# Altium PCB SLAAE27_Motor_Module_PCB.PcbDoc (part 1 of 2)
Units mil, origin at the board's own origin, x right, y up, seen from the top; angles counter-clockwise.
Board outline 2500 x 2000 mil, 4 copper layers (L1-Top Layer, L2-GND, L3-PWR, L4-Bottom Layer), stack 61.634 mil thick; 168 components, 85 nets, 418 pads, 206 vias.
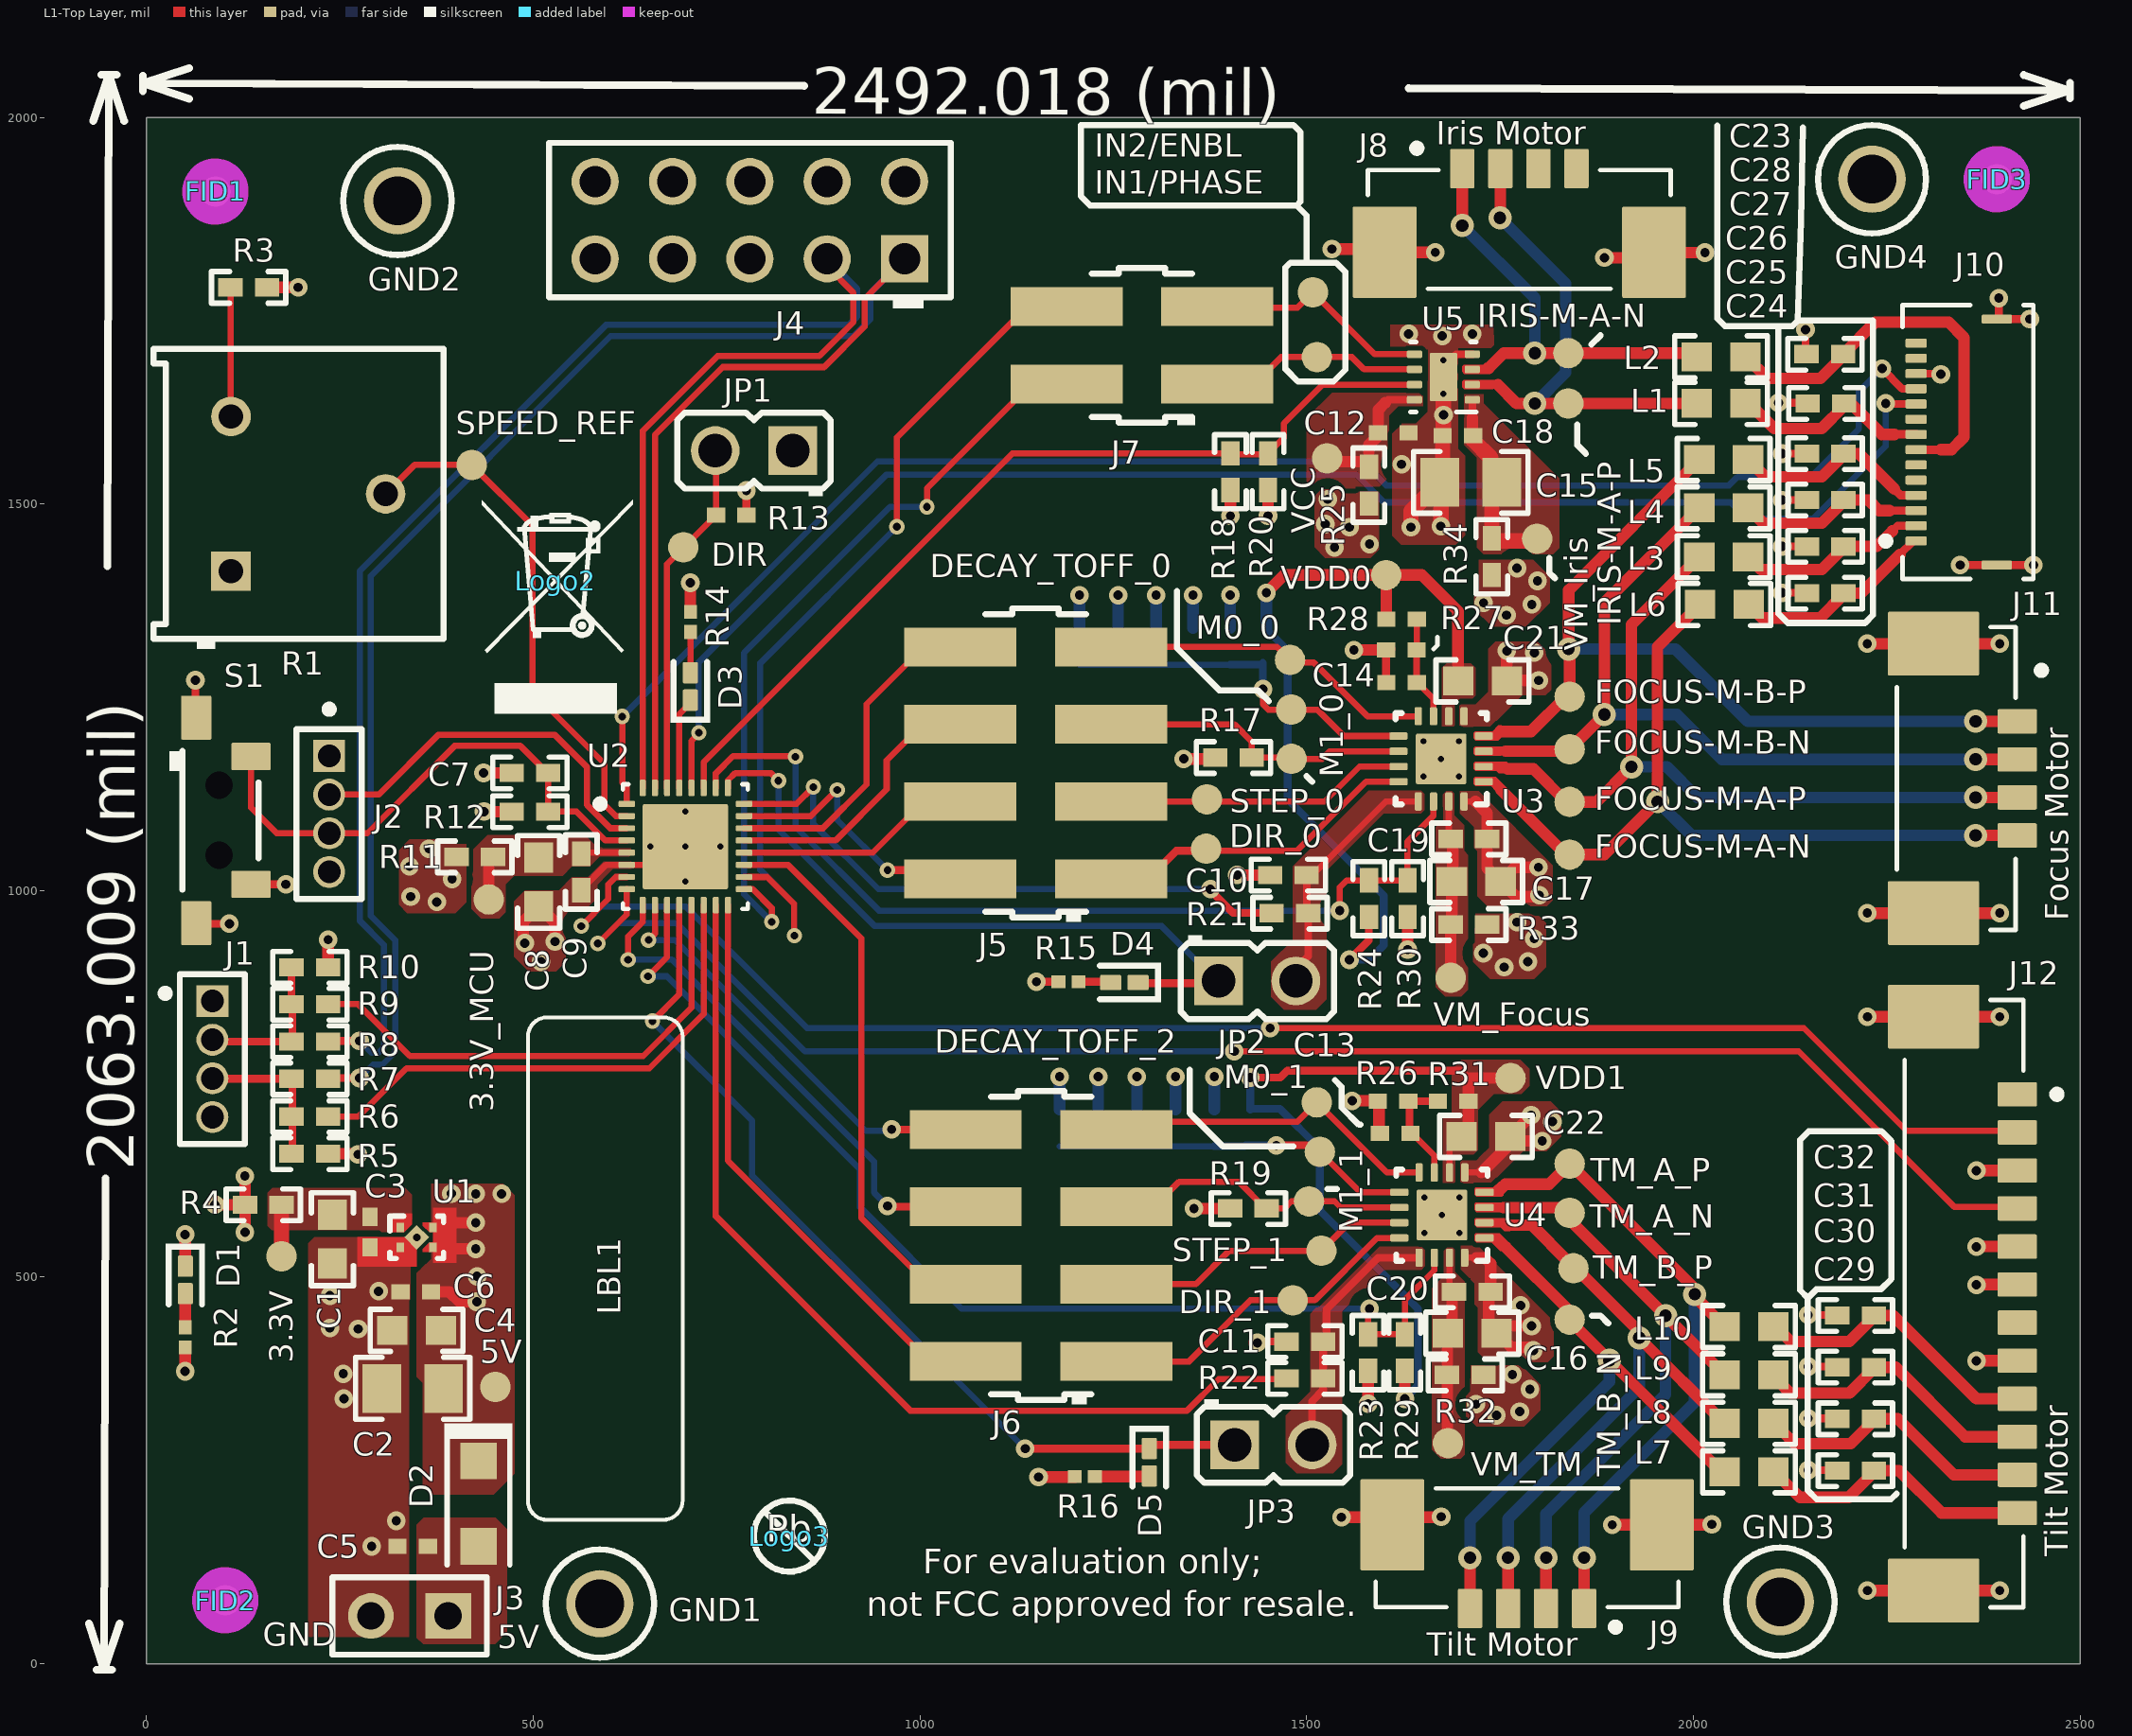
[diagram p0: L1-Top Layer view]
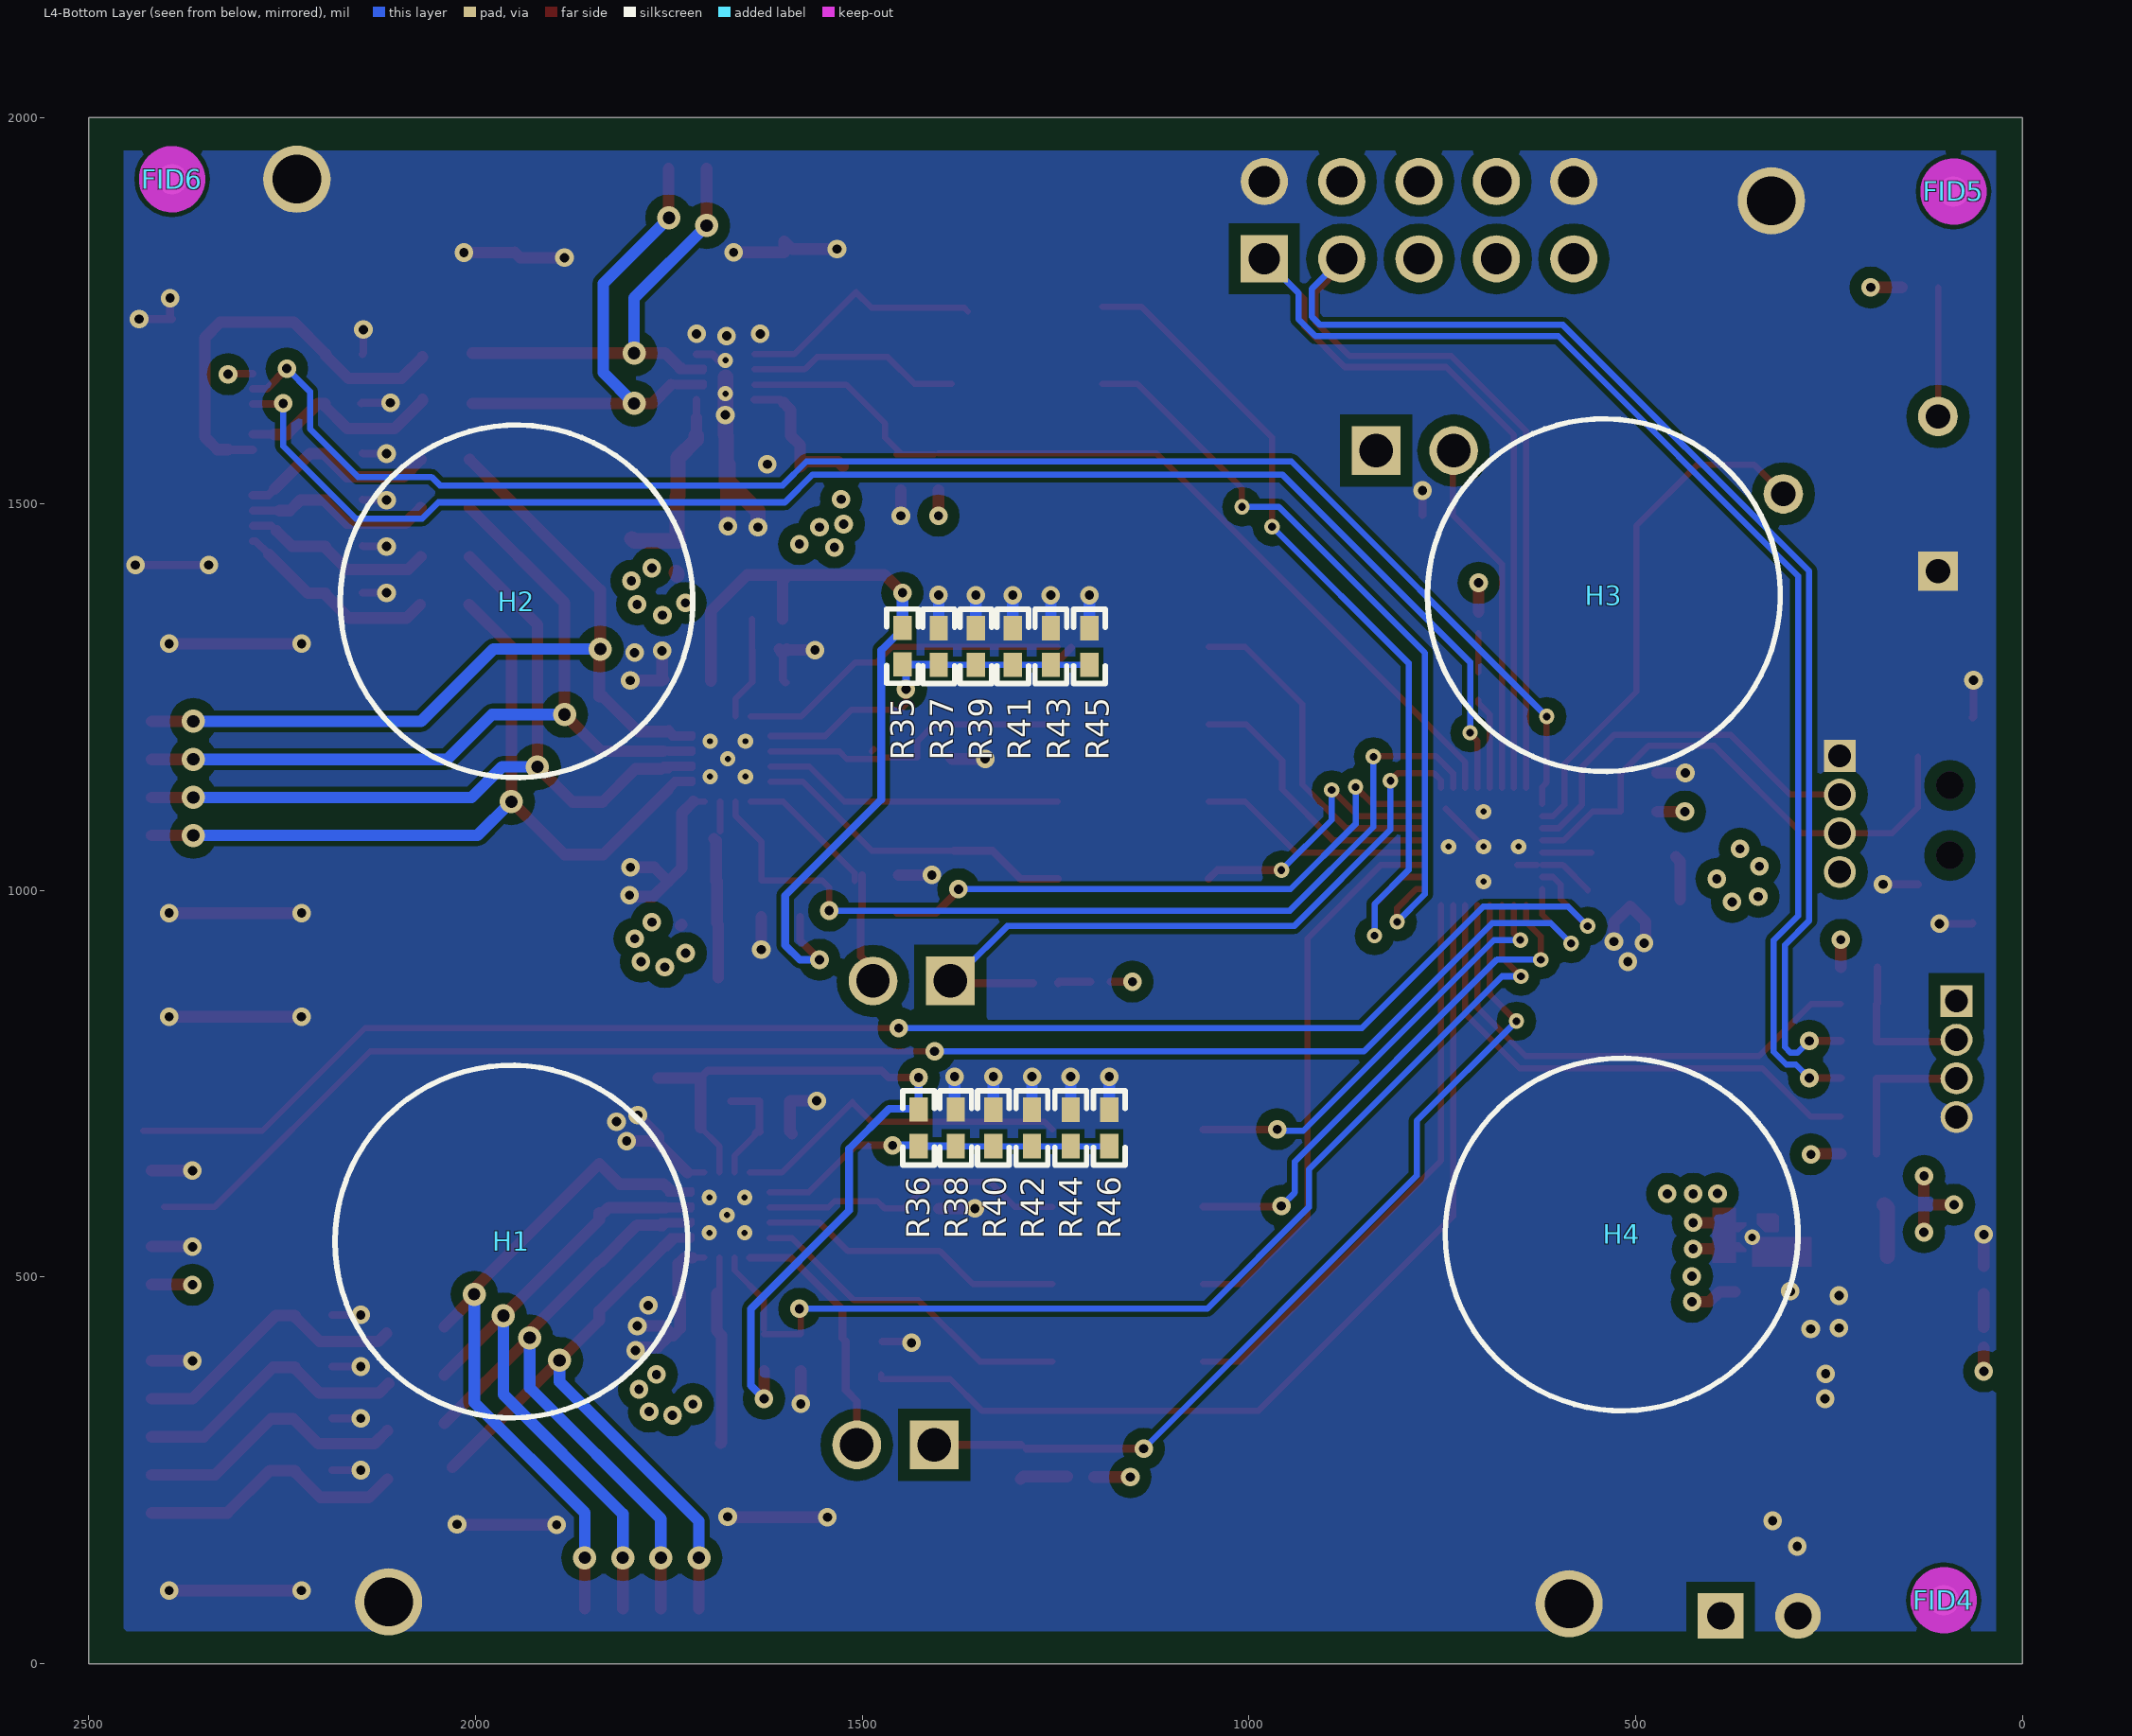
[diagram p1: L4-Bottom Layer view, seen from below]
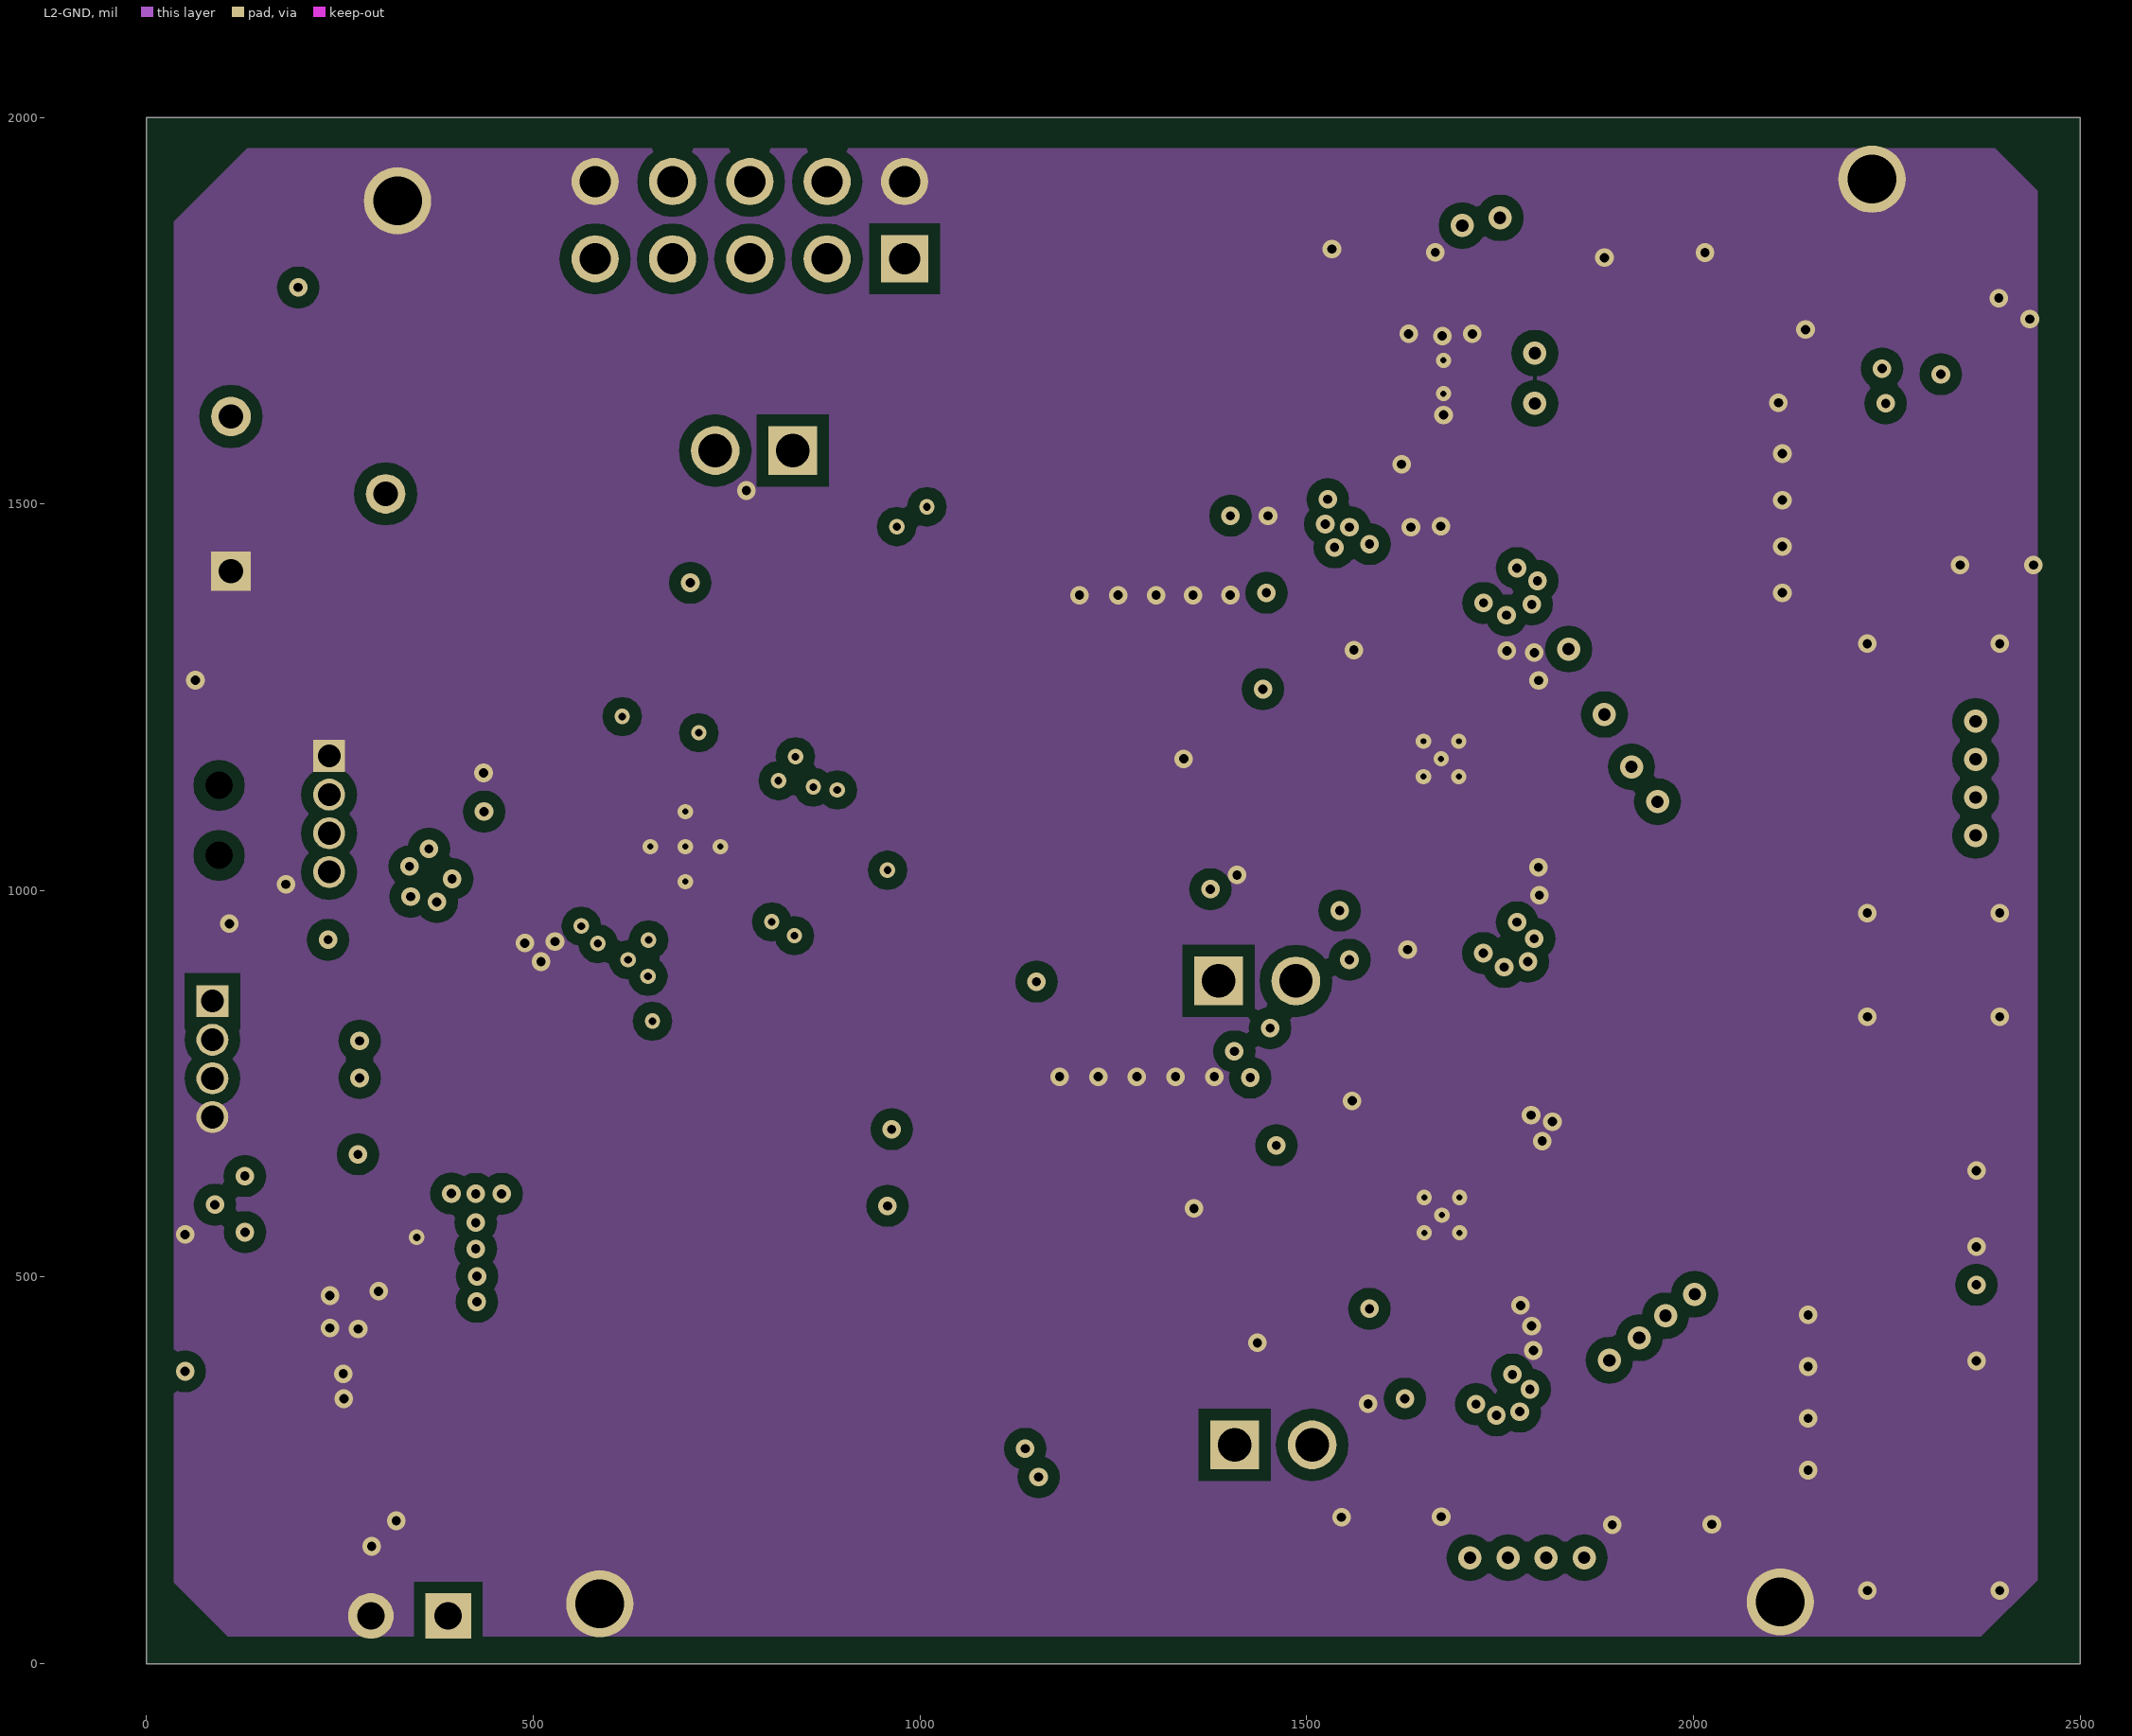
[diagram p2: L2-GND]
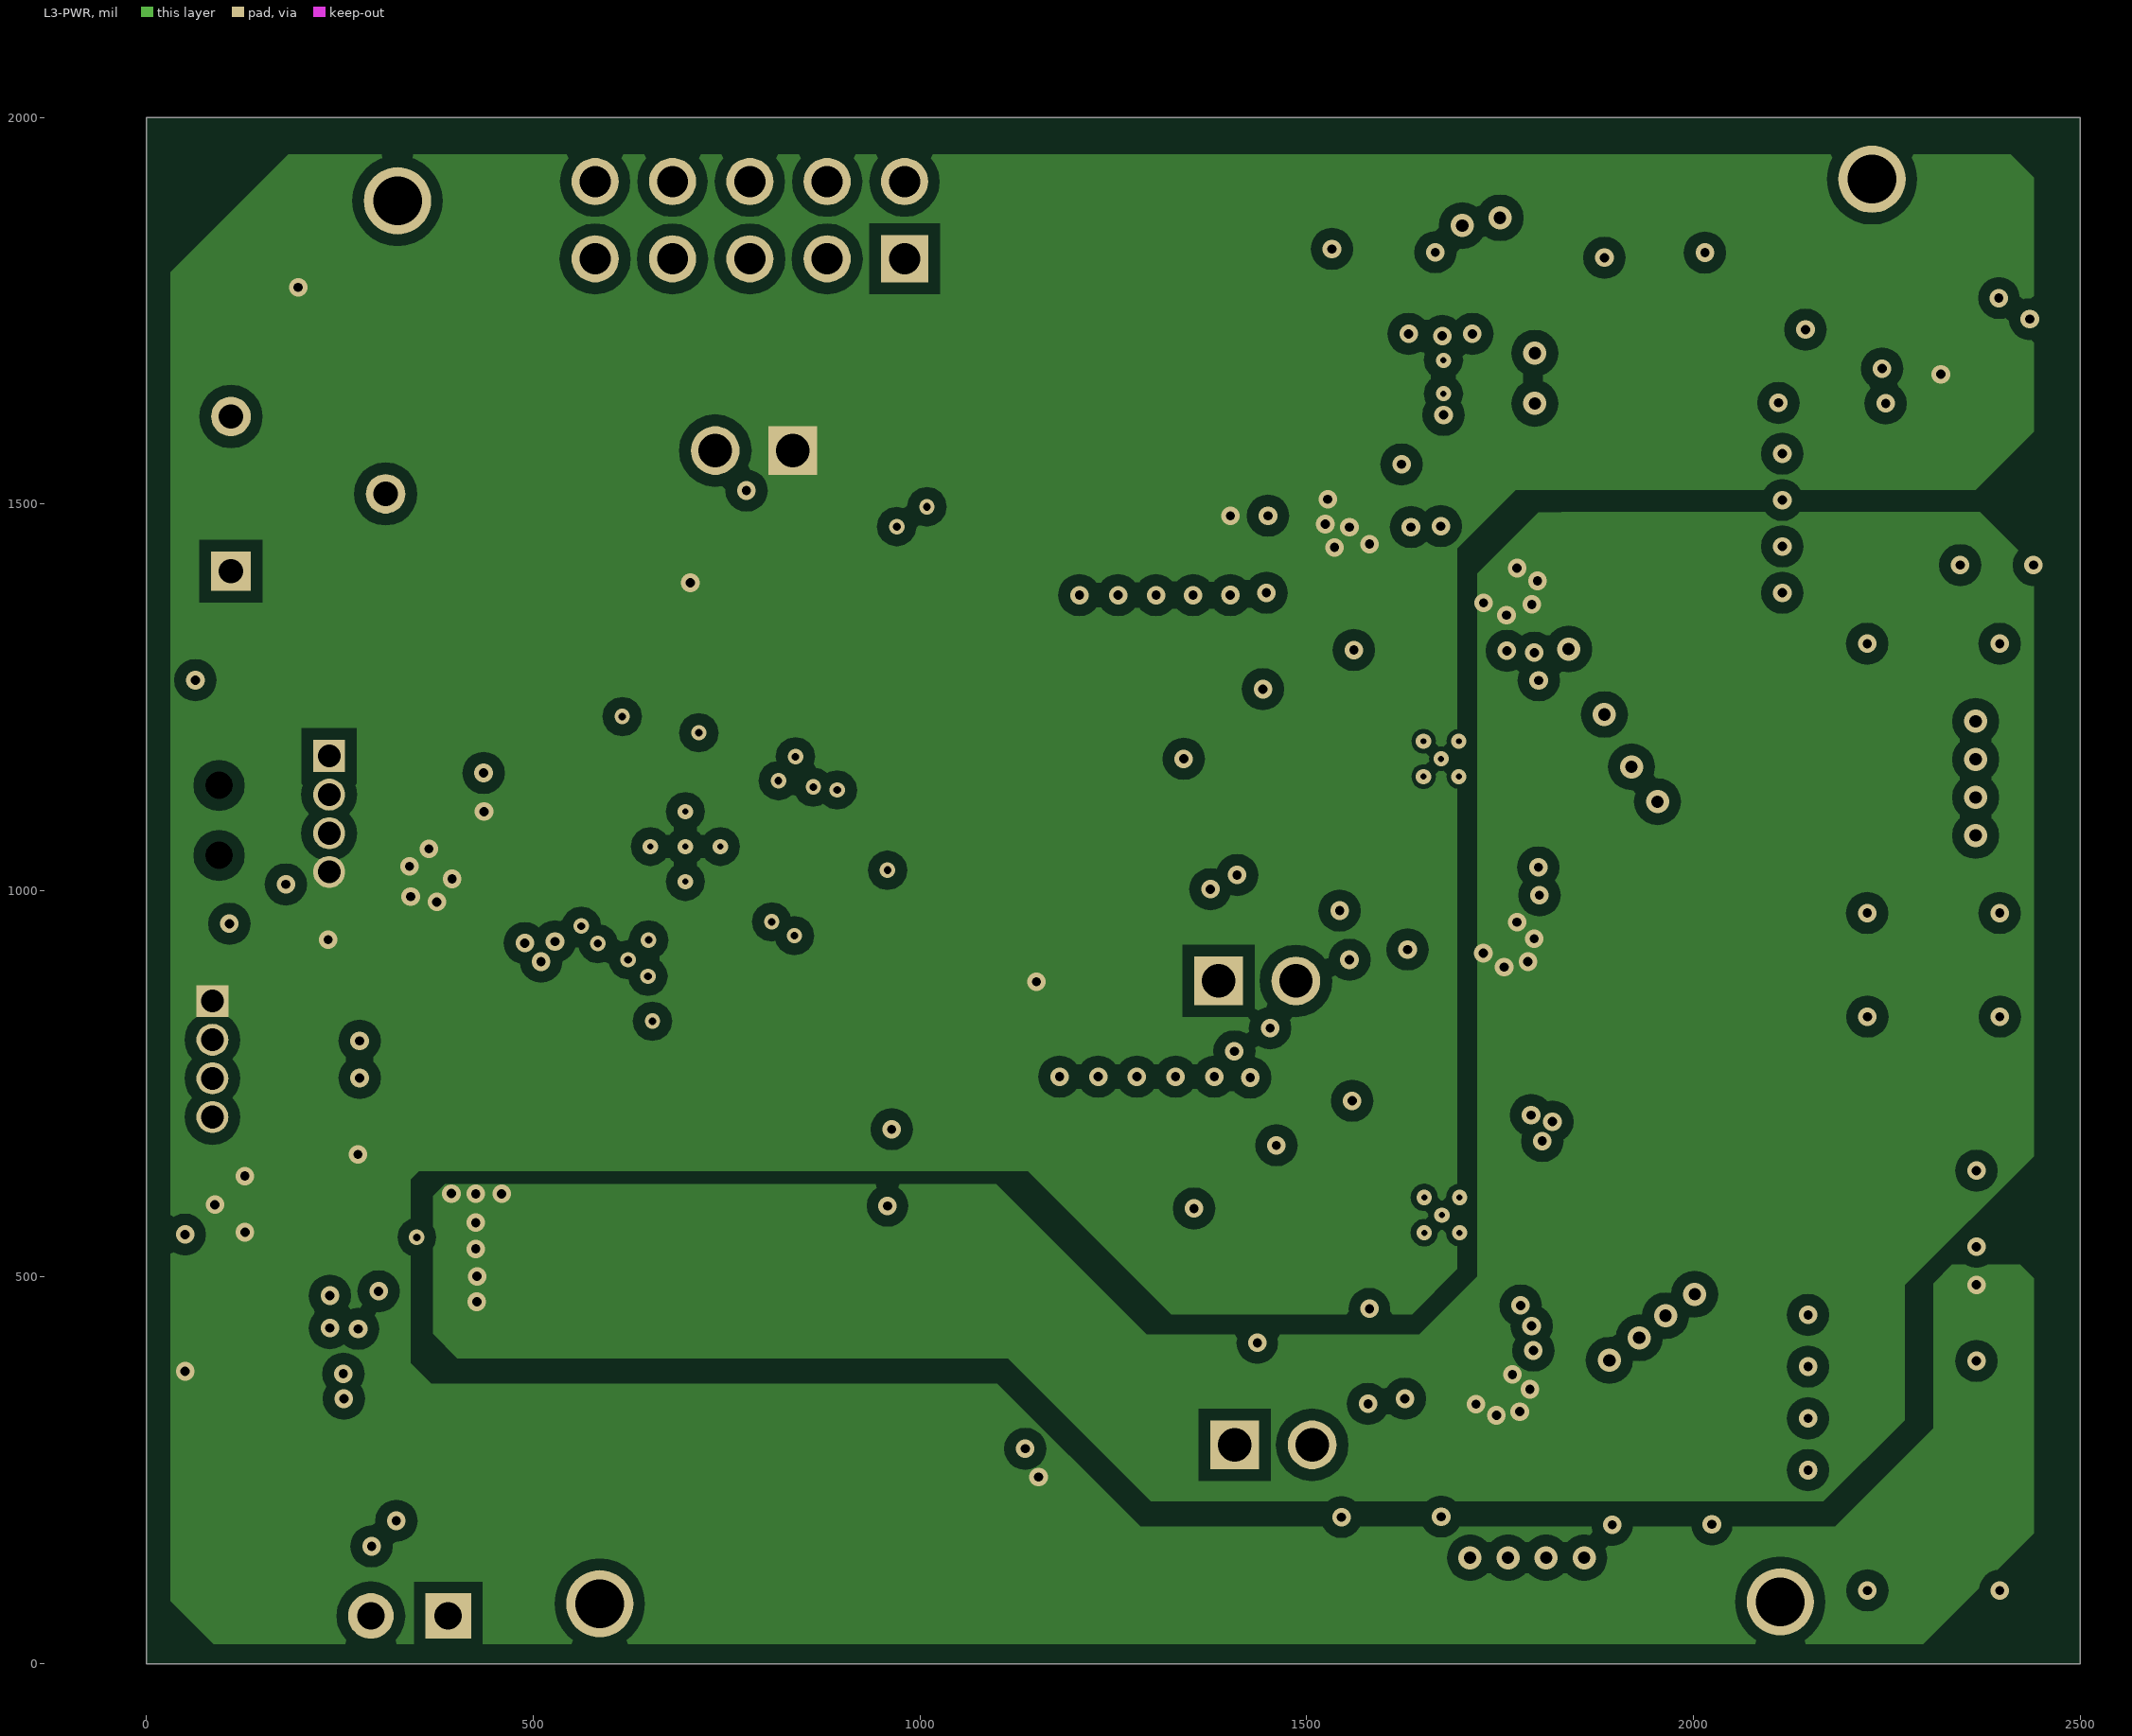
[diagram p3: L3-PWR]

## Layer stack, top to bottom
Top Solder: solder mask 0.4, Solder Resist, Dk 3.5
L1-Top Layer: signal copper 1.4
Dielectric 3: dielectric 4, FR-4 High Tg, Dk 4.2
L2-GND: signal copper 1.417
Dielectric 2: dielectric 48, FR-4 High Tg, Dk 4.2
L3-PWR: signal copper 1.417
Dielectric1: core 4, FR-4 High Tg, Dk 4.2
L4-Bottom Layer: signal copper 1.4
Bottom Solder: solder mask 0.4, Solder Resist, Dk 3.5

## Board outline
0,0 0,2000 2500,2000 2500,0

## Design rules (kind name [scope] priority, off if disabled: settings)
AcuteAngle [All] p1: minimum=4.50000000000000E+0001 checktracksonly=FALSE
AssemblyTestPointUsage [All] p1: valid=2
BoardOutlineClearance BoardOutlineClearance_MountingHoles [OnCopper and InComponentClass('Mounting Holes')] p1: gap=39.37 ignorepadtopadclearanceinfootprint=FALSE
BoardOutlineClearance BoardOutlineClearance_Poly [OnCopper and IsPoly] p2: gap=25 ignorepadtopadclearanceinfootprint=FALSE
BoardOutlineClearance [OnCopper and Not InComponentClass('Logo') and not InComponentClass('FiducialMark') and not InRegion(1000,500,4000,800) and not InPoly] p3: gap=30 ignorepadtopadclearanceinfootprint=FALSE
Clearance Clearance_3 [WithinRoom('IC_2')] p1: gap=7.87 ignorepadtopadclearanceinfootprint=TRUE except(4.2: SMDPad-SMDPad; 4.7: SMDPad-Fill SMDPad-Poly SMDPad-Region; 6.1: Via-Fill Via-Poly Via-Region; 6.55: Fill-Fill Fill-Poly Fill-Region Fill-Text Poly-Poly Poly-Region Poly-Text Region-Region Region-Text; 7.4: SMDPad-Via)
Clearance Clearance_2 [WithinRoom('IC_1')] p2: gap=7.87 ignorepadtopadclearanceinfootprint=TRUE except(4.2: SMDPad-SMDPad; 4.7: SMDPad-Fill SMDPad-Poly SMDPad-Region; 6: Arc-Region Track-Poly Track-Region Fill-Poly Poly-Poly Region-Region; 6.55: Fill-Fill Fill-Region Fill-Text Poly-Region Poly-Text Region-Text)
Clearance Clearance_1 [WithinRoom('IC')] p3: gap=7.87 ignorepadtopadclearanceinfootprint=TRUE except(4.2: SMDPad-SMDPad; 4.7: SMDPad-Fill SMDPad-Poly SMDPad-Region; 6: Arc-Poly Arc-Region Track-Poly Track-Region Region-Region; 6.1: Via-Poly Fill-Poly; 6.55: Fill-Fill Fill-Region Fill-Text Poly-Poly Poly-Region Poly-Text Region-Text; 7.4: SMDPad-Via)
Clearance Clearance_Keepouts [((IsTrack Or IsArc) And Not InPoly) And IsFree and IsKeepOut vs ((IsTrack Or IsArc) And Not InPoly) And IsFree and IsKeepOut] p4: gap=0 ignorepadtopadclearanceinfootprint=FALSE
Clearance Clearance_Poly [InPolygon] p5: gap=15 ignorepadtopadclearanceinfootprint=TRUE except(6: Arc-Fill Arc-Poly Arc-Region Track-Fill Track-Poly Track-Region SMDPad-Fill SMDPad-Poly SMDPad-Region Fill-Fill Fill-Poly Fill-Region Poly-Poly Poly-Region Region-Region)
Clearance Clearance_FiducialMark [IsKeepOut and InComponentClass('FiducialMark') vs IsPad and InComponentClass('FiducialMark')] p6: gap=0 ignorepadtopadclearanceinfootprint=FALSE
Clearance [All] p7: gap=7.87 ignorepadtopadclearanceinfootprint=TRUE except(0: Arc-SMDPad; 4.2: SMDPad-SMDPad; 4.7: SMDPad-Fill SMDPad-Poly SMDPad-Region; 6.1: Track-SMDPad; 6.5: Arc-Arc Arc-Track Track-Track; 6.55: Fill-Fill Fill-Poly Fill-Region Fill-Text Poly-Poly Poly-Region Poly-Text Region-Region Region-Text; 7.4: SMDPad-Via)
ComponentClearance ComponentClearance_MountingHoles_FiducialMarks [InComponentClass('Mounting Holes') vs InComponentClass('FiducialMark')] p1: gap=20 collisioncheckmode=3 verticalgap=10 showdistances=FALSE
ComponentClearance ComponentClearance_Shunt [InComponentClass('Header') vs InComponentClass('Shunt')] p2: gap=0 collisioncheckmode=3 verticalgap=0 showdistances=FALSE
ComponentClearance ComponentClearance_Logo [InComponentClass('Logo')] p3: gap=20 collisioncheckmode=3 verticalgap=10 showdistances=FALSE
ComponentClearance ComponentClearance_ScrewToNut [(HasFootprint('NY PMS 440 0025 PH')) vs (HasFootprint('Keystone_1902C'))] p4: gap=5 collisioncheckmode=3 verticalgap=10 showdistances=FALSE
ComponentClearance ComponentClearance_MountingHoles [InComponentClass('Mounting Holes')] p5: gap=100 collisioncheckmode=3 verticalgap=100000 showdistances=FALSE
ComponentClearance ComponentClearance_SmallPassives [HasFootprint('0201*') or HasFootprint('0402*') or HasFootprint('0508') or HasFootprint('0603*') or HasFootprint('0612') or HasFootprint('0805*') or HasFootprint('0815*') or HasFootprint('0830*') or HasFootprint('1206*') or HasFootprint('1210*') or HasFootprint('1808*') or HasFootprint('1812*') or HasFootprint('1825*') or HasFootprint('2010*') or HasFootprint('2220*') or HasFootprint('2225*') or HasFootprint('2512*') or HasFootprint('2728*') or HasFootprint('3518*') vs HasFootprint('0201*') or HasFootprint('0402*') or HasFootprint('0508') or HasFootprint('0603*') or HasFootprint('0612') or HasFootprint('0805*') or HasFootprint('0815*') or HasFootprint('0830*') or HasFootprint('1206*') or HasFootprint('1210*') or HasFootprint('1808*') or HasFootprint('1812*') or HasFootprint('1825*') or HasFootprint('2010*') or HasFootprint('2220*') or HasFootprint('2225*') or HasFootprint('2512*') or HasFootprint('2728*') or HasFootprint('3518*')] p6: gap=14.96 collisioncheckmode=3 verticalgap=10 showdistances=FALSE
ComponentClearance ComponentClearance_THtoSMT [IsThruComponent vs IsSMTComponent] p7: gap=20 collisioncheckmode=3 verticalgap=20 showdistances=FALSE
ComponentClearance ComponentClearance_THtoTH [IsThruComponent vs IsThruComponent] p8: gap=20 collisioncheckmode=3 verticalgap=20 showdistances=FALSE
ComponentClearance [All] p9: gap=20 collisioncheckmode=3 verticalgap=10 showdistances=FALSE
DiffPairsRouting [All] p1: maxlimit=100 minlimit=10 mostfreqgap=10 toplayer_minwidth=15 toplayer_maxwidth=15 toplayer_prefwidth=15 midlayer1_minwidth=15 midlayer1_maxwidth=15 midlayer1_prefwidth=15 midlayer2_minwidth=15 midlayer2_maxwidth=15 midlayer2_prefwidth=15 bottomlayer_minwidth=15 bottomlayer_maxwidth=15 bottomlayer_prefwidth=15 maxuncoupledlength=1000
FabricationTestPointUsage TestPointUsage [All] p1: valid=2 allowmultiple=FALSE
FabricationTestpoint Testpoint [All] p1: side=3 testpointundercomponent=TRUE minsize=40 maxsize=100 preferedsize=60 minholesize=0 maxholesize=40 preferedholesize=32 testpointgrid=1 allowsidetop=TRUE allowsidebottom=TRUE usegrid=TRUE gridtolerance=0.01
FanoutControl Fanout_LCC [IsLCC] p1: bgadir=Out bgaviamode=Centered fanoutstyle=Auto fanoutdirection=Alternating viagrid=1 // Fanout_LCC (Default Rule)
FanoutControl Fanout_BGA [IsBGA] p2: bgadir=Out bgaviamode=Centered fanoutstyle=Auto fanoutdirection=Alternating viagrid=1 // Fanout_BGA (Default Rule)
FanoutControl Fanout_Default [All] p4: bgadir=Out bgaviamode=Centered fanoutstyle=Auto fanoutdirection=Alternating viagrid=1 // Fanout_Default (Default Rule)
FanoutControl Fanout_Small [(CompPinCount < 5)] p5: bgadir=Out bgaviamode=Centered fanoutstyle=Auto fanoutdirection=OutThenIn viagrid=1 // Fanout_Small (Default Rule)
HoleSize [All] p1: absolutevalues=TRUE maxlimit=251 minlimit=7.87 maxpercent=80.000 minpercent=20.000
MinimumAnnularRing MinimumAnnularRing_ThermalPadVias [IsVia and InAnyComponent] p1: minimumring=5.91
MinimumAnnularRing [All] p2: minimumring=4
MinimumSolderMaskSliver MinimumSolderMaskSliver_Logo [InComponentClass('Logo') vs InComponentClass('Logo')] p1: minsoldermaskwidth=0.7
MinimumSolderMaskSliver [All] p2: minsoldermaskwidth=3.94
PlaneConnect [All] p1: planeconnectstyle=Direct reliefexpansion=10 reliefentries=4 reliefconductorwidth=10 reliefairgap=10
PolygonConnect [All] p1: connectstyle=Direct reliefconductorwidth=10 reliefentries=4 polygonreliefangle="90 Angle" airgapwidth=10
RoomDefinition MCU_&_Motor_Drivers [InComponentClass('MCU_&_Motor_Drivers')] p1: confinementstyle=ConfineIn formatcopy=TRUE lockcomponents=FALSE outline 258.05,640.54 449.05,640.54 449.05,472.13 258.05,472.13
RoomDefinition IC_1 [False] p2: confinementstyle=ConfineIn formatcopy=TRUE lockcomponents=FALSE outline 1595.11,653.75 1786.11,653.75 1786.11,485.33 1595.11,485.33
RoomDefinition IC [False] p3: confinementstyle=ConfineIn formatcopy=TRUE lockcomponents=FALSE outline 1583,1252 1774,1252 1774,1083.58 1583,1083.58
RoutingVias ThermalPadVias [IsVia and InAnyComponent] p1: holewidth=7.87 width=19.68 viastyle="Through Hole" minholewidth=7.87 minwidth=19.68 maxholewidth=12.99 maxwidth=23.62
RoutingVias [All] p2: holewidth=16 width=34 viastyle="Through Hole" minholewidth=7.87 minwidth=20 maxholewidth=40 maxwidth=65
SilkToBoardRegionClearance [Not ((IsComment or IsDesignator) And (Hide <> 'False')) and not InRegion(1000,500,4000,800)] p1:
SilkToSilkClearance SilkToSilkClearance_Pb-FreeLogo [(HasFootprint('Pb-Free_Overlay_Medium') OR HasFootprint('Pb-Free_Overlay_Small')) vs (HasFootprint('Pb-Free_Overlay_Medium') OR HasFootprint('Pb-Free_Overlay_Small'))] p1: silktosilkclearance=0
SilkToSilkClearance [All] p2: silktosilkclearance=2
SilkToSolderMaskClearance SilkToComponentPadClearance [(IsPad or IsFill or IsRegion) and InAnycomponent] p1: minsilkscreentomaskgap=2.5 clearancetoexposedcopper=TRUE
SilkToSolderMaskClearance "Silk to Solder Mask Opening" [All] p2: minsilkscreentomaskgap=2 clearancetoexposedcopper=FALSE
SolderMaskExpansion [All] p1: expansion=1.97
UnRoutedNet [All] p1: checkbadconnections=TRUE
Width Width_1 [InNetClass('pwr')] p1: maxlimit=25 minlimit=15 preferedwidth=20
Width [All] p2: maxlimit=100 minlimit=6 preferedwidth=10 checkconnectedcopper=TRUE
14 further rules are at their usual default settings.

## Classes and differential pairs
component class Label: LBL1
component class AssemblyNote: ZZ1 ZZ2 ZZ3 ZZ4
component class FiducialMark: FID1 FID2 FID3 FID4 FID5 FID6
component class Camera_Motor_Module_Hardware: FID1 FID2 FID3 FID4 FID5 FID6 H1 H2 H3 H4 LBL1 Logo2 Logo3 ZZ1 ZZ2 ZZ3 ZZ4
component class Header: J1 J2 J5 J6 J7 JP1 JP2 JP3

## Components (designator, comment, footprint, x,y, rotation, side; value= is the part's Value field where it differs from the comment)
3.3V "TP_SM_1MM" TP_SM_1MM 174.47,526.92 r90 top
3.3V_MCU "TP_SM_1MM" TP_SM_1MM 442.38,988.38 r0 top
5V "TP_SM_1MM" TP_SM_1MM 451,358 r90 top
C1 "GRM188R71C105KA12D" 0603 240.1,548.99 r270 top value=1uF
C2 "C2012X7R1V475K125AC" 0805_HV 344.01,356.04 r180 top value=4.7uF
C3 "" 0402#1 289.01,558.1 r90 top value=0.1uF
C4 "GRM188R71C105KA12D" 0603 349.01,431.04 r180 top value=1uF
C5 "" 0402#1 344.01,151.76 r0 top value=0.1uF
C6 "" 0402#1 348,481.09 r0 top value=0.1uF
C7 "885012205044" 0402#2 495.62,1152 r180 top value=1000pF
C8 "GRM188Z71A106MA73D" 0603 507,1011.15 r270 top value=10uF
C9 "" 0402#2 562,1023.89 r90 top value=0.1uF
C10 "0402YC101KAT2A" 0402#2 1476.38,1020 r180 top value=100pF
C11 "0402YC101KAT2A" 0402#2 1497.62,416.55 r180 top value=100pF
C12 "" 0402#1 1612,1592 r180 top value=0.1uF
C13 "" 0402#1 1614.4,685.67 r0 top value=0.1uF
C14 "" 0402#1 1622.71,1269.07 r0 top value=0.1uF
C15 "C2012X7R1V475K125AC" 0805_HV 1712.23,1527.95 r180 top value=4.7uF
C16 "GRM188Z71C475KE21D" 0603 1714.2,427.36 r0 top value=4.7uF
C17 "GRM188Z71C475KE21D" 0603 1719.21,1011.72 r0 top value=4.7uF
C18 "" 0402#1 1695.38,1588.28 r0 top value=0.1uF
C19 "GRM155R71H103KA88D" 0402#2 1709.76,1066.72 r0 top value=0.01uF
C20 "GRM155R71H103KA88D" 0402#2 1714.2,481.04 r0 top value=0.01uF
C21 "C1608X7R1H474K080AC" 0603 1727.32,1270.98 r0 top value=0.47uF
C22 "C1608X7R1H474K080AC" 0603 1731.76,681.84 r0 top value=0.47uF
C23 "CGA2B2X7R1H332K050BA" 0402#2 2170,1693.67 r180 top value=3300pF
C24 "CGA2B2X7R1H332K050BA" 0402#2 2170.38,1384.63 r0 top value=3300pF
C25 "CGA2B2X7R1H332K050BA" 0402#2 2170.38,1445 r0 top value=3300pF
C26 "CGA2B2X7R1H332K050BA" 0402#2 2170.38,1505 r0 top value=3300pF
C27 "CGA2B2X7R1H332K050BA" 0402#2 2170.38,1565 r180 top value=3300pF
C28 "CGA2B2X7R1H332K050BA" 0402#2 2171.38,1630 r180 top value=3300pF
C29 "CGA2B2X7R1H332K050BA" 0402#2 2209.68,249.63 r180 top value=3300pF
C30 "CGA2B2X7R1H332K050BA" 0402#2 2209.68,316.56 r180 top value=3300pF
C31 "CGA2B2X7R1H332K050BA" 0402#2 2209.68,383.49 r0 top value=3300pF
C32 "CGA2B2X7R1H332K050BA" 0402#2 2209.68,450.42 r0 top value=3300pF
D1 "APHHS1005CGCK" APHHS1005_Green 50,496.26 r90 top value=Green
D2 "DB2W40200L" SOD-123F 429.01,206.88 r270 top value=40V
D3 "APHHS1005SURCK" APHHS1005_Red 703,1264 r270 top value=Red
D4 "APHHS1005SURCK" APHHS1005_Red 1264.28,881 r0 top value=Red
D5 "APHHS1005SURCK" APHHS1005_Red 1296.5,260.5 r90 top value=Red
DECAY_TOFF_0 "TP_SM_1MM" TP_SM_1MM 1480,1233.99 r0 top
DECAY_TOFF_2 "TP_SM_1MM" TP_SM_1MM 1517,662 r0 top
DIR "TP_SM_1MM" TP_SM_1MM 694,1444 r0 top
DIR_0 "TP_SM_1MM" TP_SM_1MM 1370,1054 r0 top
DIR_1 "TP_SM_1MM" TP_SM_1MM 1482,470 r270 top
FID1 "Fiducial" Fiducial10-20 89,1904 r0 top
FID2 "Fiducial" Fiducial10-20 101.64,81.95 r0 top
FID3 "Fiducial" Fiducial10-20 2392.4,1920 r0 top
FID4 "Fiducial" Fiducial10-20 101.64,81.95 r180 bottom
FID5 "Fiducial" Fiducial10-20 89,1904 r180 bottom
FID6 "Fiducial" Fiducial10-20 2392.4,1920 r180 bottom
FOCUS-M-A-N "TP_SM_1MM" TP_SM_1MM 1840,1046.44 r0 top
FOCUS-M-A-P "TP_SM_1MM" TP_SM_1MM 1840,1114.54 r0 top
FOCUS-M-B-N "TP_SM_1MM" TP_SM_1MM 1840,1182.65 r0 top
FOCUS-M-B-P "TP_SM_1MM" TP_SM_1MM 1840,1250.75 r0 top
GND1 "GND" Keystone5005 586,77.55 r0 top
GND2 "GND" Keystone5005 324.33,1892 r0 top
GND3 "GND" Keystone5005 2112.47,80 r0 top
GND4 "GND" Keystone5005 2231,1920 r180 top
H1 "SJ-5303 (CLEAR)" Bumpon_SJ5003Transparent 1953.63,546 r180 bottom
H2 "SJ-5303 (CLEAR)" Bumpon_SJ5003Transparent 1947,1374 r180 bottom
H3 "SJ-5303 (CLEAR)" Bumpon_SJ5003Transparent 541,1382 r180 bottom
H4 "SJ-5303 (CLEAR)" Bumpon_SJ5003Transparent 518,555.1 r180 bottom
IN1/PHASE "TP_SM_1MM" TP_SM_1MM 1513.28,1690 r180 top
IN2/ENBL "TP_SM_1MM" TP_SM_1MM 1508,1773.77 r180 top
IRIS-M-A-N "TP_SM_1MM" TP_SM_1MM 1838.3,1695 r0 top
IRIS-M-A-P "TP_SM_1MM" TP_SM_1MM 1838.3,1630 r0 top
J1 "GRPB041VWVN-RC" Sullins_GRPB041VWVN-RC 85,782 r270 top
J2 "GRPB041VWVN-RC" Sullins_GRPB041VWVN-RC 236,1099 r270 top
J3 "Header 2" HDR1X2 389.92,61.69 r180 top value="2-Pin Header"
J4 "PPTC052LFBN-RC" Sullins_xPxC052LFBN 780,1867 r180 top
J5 "TSM-104-01-L-DV" Samtec_TSM-104-01-x-DV 1149.56,1165 r180 top
J6 "TSM-104-01-L-DV" Samtec_TSM-104-01-x-DV 1156.56,540.87 r180 top
J7 "TSM-102-01-L-DV" Samtec_TSM-102-01-x-DV 1287,1705.18 r180 top
J8 "533980471" FP-533980471_HDR4-MFG 1775,1855 r180 top
J9 "533980471" FP-533980471_HDR4-MFG 1785,150 r0 top
J10 "5034801400" FP-5034801400_SMD_8MM7_3MM6-MFG 2355,1580 r90 top
J11 "533980471" FP-533980471_HDR4-MFG 2340,1145 r90 top
J12 "533981271" FP-533981271_HDR12-MFG 2350,465.7 r90 top
JP1 "961102-6404-AR" 3M_961102-6404-AR 785.23,1569 r180 top
JP2 "961102-6404-AR" 3M_961102-6404-AR 1436.1,883 r0 top
JP3 "961102-6404-AR" 3M_961102-6404-AR 1457,283 r0 top
L1 "BLM18SG221TN1D" 0603 2035.76,1630 r0 top value="220 ohm"
L2 "BLM18SG221TN1D" 0603 2035.76,1690 r0 top value="220 ohm"
L3 "BLM18SG221TN1D" 0603 2039.2,1431.55 r0 top value="220 ohm"
L4 "BLM18SG221TN1D" 0603 2039.2,1495 r0 top value="220 ohm"
L5 "BLM18SG221TN1D" 0603 2039.2,1557.36 r0 top value="220 ohm"
L6 "BLM18SG221TN1D" 0603 2040,1370 r0 top value="220 ohm"
L7 "BLM18SG221TN1D" 0603 2072,248.1 r0 top value="220 ohm"
L8 "BLM18SG221TN1D" 0603 2072,310.81 r0 top value="220 ohm"
L9 "BLM18SG221TN1D" 0603 2072,373.56 r0 top value="220 ohm"
L10 "BLM18SG221TN1D" 0603 2072,435.95 r0 top value="220 ohm"
LBL1 "THT-14-423-10" Label_650x200 593,511 r90 top
Logo2 "WEEE logo" WEEE_Minimum 529,1401 r0 top
Logo3 "Pb-Free Symbol" Pb-Free_Overlay_Small 831,165 r0 top
M0_0 "TP_SM_1MM" TP_SM_1MM 1478.42,1298.19 r0 top
M0_1 "TP_SM_1MM" TP_SM_1MM 1513,726 r270 top
M1_0 "TP_SM_1MM" TP_SM_1MM 1480.4,1170.25 r0 top
M1_1 "TP_SM_1MM" TP_SM_1MM 1503,598 r270 top
R1 "3310Y-001-103L" Bourns_3310Y 209,1513 r90 top value=10kohm
R2 "RC0201FR-073K3L" 0201 50,422.01 r270 top value=3.30k
R3 "ERJ-2GE0R00X" 0402#2 132,1780 r0 top value=0
R4 "ERJ-2GE0R00X" 0402#2 150.85,593.58 r180 top value=0
R5 "CRCW040210K0JNED" 0402#2 211,659.5 r0 top value=10k
R6 "ERJ-2GE0R00X" 0402#2 211,707.5 r0 top value=0
R7 "ERJ-2GE0R00X" 0402#2 211,756.5 r180 top value=0
R8 "ERJ-2GE0R00X" 0402#2 211,804.5 r180 top value=0
R9 "ERJ-2GE0R00X" 0402#2 211,852.98 r0 top value=0
R10 "CRCW040210K0JNED" 0402#2 211,900.5 r0 top value=10k
R11 "ERJ-2GE0R00X" 0402#2 424.38,1043.38 r0 top value=0
R12 "RC0402FR-0747KL" 0402#2 495.62,1102 r180 top value=47.0k
R13 "0402" 0402#1 755.89,1485.33 r0 top value=1K
R14 "RC0201FR-073K3L" 0201 703.12,1347.45 r90 top value=3.30k
R15 "RC0201FR-073K3L" 0201 1192,882.05 r180 top value=3.30k
R16 "RC0201FR-073K3L" 0201 1213,242 r180 top value=3.30k
R17 "RC0402FR-07330KL" 0402#2 1405.31,1171.87 r0 top value=330k
R18 "ERJ-2GE0R00X" 0402#2 1401.41,1541.62 r90 top value=0
R19 "RC0402FR-07330KL" 0402#2 1424.64,588.73 r0 top value=330k
R20 "ERJ-2GE0R00X" 0402#2 1450,1541.62 r270 top value=0
R21 "CRCW0402200KFKED" 0402#2 1478.38,970.79 r0 top value=200k
R22 "CRCW0402200KFKED" 0402#2 1497.61,369 r0 top value=200k
R23 "ERJ-2GE0R00X" 0402#2 1579.32,402.36 r270 top value=0
R24 "ERJ-2GE0R00X" 0402#2 1580.46,989.52 r90 top value=0
R25 "ERJ-2GE0R00X" 0402#2 1580.46,1524.26 r90 top value=0
R26 "0402" 0402#1 1611.63,727.36 r180 top value=1K
R27 "0402" 0402#1 1622.46,1311.05 r180 top value=1K
R28 "0402" 0402#1 1622.71,1351.14 r0 top value=1K
R29 "ERJ-2GE0R00X" 0402#2 1626.94,402.36 r90 top value=0
R30 "ERJ-2GE0R00X" 0402#2 1630.46,989.52 r270 top value=0
R31 "0402" 0402#1 1689.4,727.36 r180 top value=1K
R32 "ERJ-2GE0R00X" 0402#2 1705,373.59 r180 top value=0
R33 "ERJ-2GE0R00X" 0402#2 1709.76,956.09 r180 top value=0
R34 "ERJ-2GE0R00X" 0402#2 1739.39,1431.79 r90 top value=0
R35 "ERJ-2GE0R00X" 0402#2 1448,1316 r90 bottom value=0
R36 "ERJ-2GE0R00X" 0402#2 1427,693 r90 bottom value=0
R37 "ERJ-2GE0R00X" 0402#2 1401.09,1315.64 r270 bottom value=0
R38 "ERJ-2GE0R00X" 0402#2 1379,693 r270 bottom value=0
R39 "CRCW040214K7FKED" 0402#2 1353.11,1315.64 r270 bottom value=14.7k
R40 "CRCW040214K7FKED" 0402#2 1330.47,692.83 r270 bottom value=14.7k
R41 "CRCW040244K2FKED" 0402#2 1305.27,1315.64 r270 bottom value=44.2k
R42 "CRCW040244K2FKED" 0402#2 1280.47,692.83 r270 bottom value=44.2k
R43 "RMCF0402FT100K" 0402#2 1256.18,1315.64 r270 bottom value=100k
R44 "RMCF0402FT100K" 0402#2 1230.47,692.83 r270 bottom value=100k
R45 "CRCW0402249KFKED" 0402#2 1206.18,1315.64 r270 bottom value=249k
R46 "CRCW0402249KFKED" 0402#2 1180.47,692.83 r270 bottom value=249k
S1 "1188E-1K2-V-TR" SW_1188E 107.44,1090.65 r0 top
SPEED_REF "TP_SM_1MM" TP_SM_1MM 420.47,1550.47 r0 top
STEP_0 "TP_SM_1MM" TP_SM_1MM 1371,1118 r0 top
STEP_1 "TP_SM_1MM" TP_SM_1MM 1519,534 r270 top
TM_A_N "TP_SM_1MM" TP_SM_1MM 1840,583.15 r0 top
TM_A_P "TP_SM_1MM" TP_SM_1MM 1840,646.7 r0 top
TM_B_N "TP_SM_1MM" TP_SM_1MM 1840,445.06 r0 top
TM_B_P "TP_SM_1MM" TP_SM_1MM 1845,511.31 r0 top
U1 "TLV74233PDQNR" DQN0004A 349.28,551.41 r0 top
U2 "MSP430FR2155TRSMT" RSM0032B-MFG 696.6,1056.86 r0 top
U3 "DRV8428RTER" RTE0016J 1673.89,1170.25 r180 top
U4 "DRV8428RTER" RTE0016J 1674.88,580.16 r180 top
U5 "DRV8837CDSG" DSG0008A 1676.8,1664.15 r180 top
VCC "TP_SM_1MM" TP_SM_1MM 1526.38,1559 r90 top
VDD0 "TP_SM_1MM" TP_SM_1MM 1602.77,1408 r90 top
VDD1 "TP_SM_1MM" TP_SM_1MM 1763.53,757.36 r90 top
VM_Focus "TP_SM_1MM" TP_SM_1MM 1686.14,887.07 r90 top
VM_Iris "TP_SM_1MM" TP_SM_1MM 1797.92,1455 r90 top
VM_TM "TP_SM_1MM" TP_SM_1MM 1682.7,285.3 r90 top
ZZ1 "These assemblies must comply with workmanship standards IPC-A-610 Class 2, unless otherwise specified." AssemblyNote -915,3552 r0 top
ZZ2 "These assemblies must be clean and free from flux and all contaminants. Use of no clean flux is not acceptable." AssemblyNote -915,3640.56 r0 top
ZZ3 "These assemblies are ESD sensitive, ESD precautions shall be observed." AssemblyNote -915,3729.11 r0 top
ZZ4 "This Assembly Note is for PCB labels only" AssemblyNoteLabel -915,3838 r0 top

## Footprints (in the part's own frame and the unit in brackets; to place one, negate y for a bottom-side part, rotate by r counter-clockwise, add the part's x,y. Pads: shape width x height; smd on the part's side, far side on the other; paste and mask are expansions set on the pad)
3M_961102-6404-AR [mm] "Header, 2.54mm, 2x1, TH"
  rect 1.6x1.6 hole 1.1: 1(-1.27,0)
  round 1.6 hole 1.1: 2(1.27,0)
  silkscreen extent -2.52,-1.25 2.52,1.5, body extent -2.52,-1.25 2.52,1.25, height 8.5
0201 [mm] "Data from Kemet datasheet CC101_COM dated 7/28/11"
  rect 0.46x0.42 smd mask+0.048: 1(-0.33,0) 2(0.33,0)
  body extent -0.31,-0.16 0.31,0.16, height 0.26
0402#1 [mm] "Chip Capacitor, Body 1.0x0.5mm, IPC High Density"
  rect 0.6x0.5 smd: 1(-0.5,0) 2(0.5,0)
  body extent -0.55,-0.3 0.55,0.3, height 1.3
0402#2 [mm] "0402 from SM-752 data"
  rect 0.8x0.6 smd: 1(-0.6,0) 2(0.6,0)
  silkscreen extent -1.22,-0.52 1.22,0.52, body extent -0.55,-0.3 0.55,0.3, height 0.6
0603 [mm] "0603 from SM-752 data"
  rect 1x0.95 smd: 1(-0.8,0) 2(0.8,0)
  silkscreen extent -1.52,-0.69 1.52,0.69, body extent -0.87,-0.47 0.87,0.47, height 1
0805_HV [mil] "0805 with 30mil clearance between pads"
  rect 50x63 smd: 1(-40,0) 2(40,0)
  silkscreen extent -74,-40 74,40, body extent -43,-29 43,29, height 57
APHHS1005_Green [mm] "SMD, 2-Leads, Body 1x0.5mm"
  rrect20% 0.7x0.5 smd: 1(-0.45,0) 2(0.45,0)
  silkscreen extent -0.8,-0.65 1.2,0.65, body extent -0.5,-0.25 0.5,0.25, height 0.5
APHHS1005_Red [mm] "SMD, 2-Leads, Body 1x0.5mm"
  rrect20% 0.7x0.5 smd: 1(-0.45,0) 2(0.45,0)
  silkscreen extent -0.8,-0.65 1.2,0.65, body extent -0.5,-0.25 0.5,0.25, height 0.5
AssemblyNote [mil] "Assembly Note"
AssemblyNoteLabel [mil] "Assembly Note for PCB Labels"
Bourns_3310Y [mm] "TH, 3-Leads, Body 9.53x9.53mm"
  rect 1.3x1.3 hole 0.8: 1(-2.54,2.54)
  round 1.3 hole 0.8: 2(0,-2.54) 3(2.54,2.54)
  silkscreen extent -5.1,-4.45 4.76,5.08, body extent -4.76,-4.44 4.76,5.08, height 17.21
Bumpon_SJ5003Transparent [mil] "3M Hemispherical Bumpon transparent"
  round 1 on Mech4: 0(0,0)
  silkscreen extent -228,-228 228,228, body extent -219,-219 219,219, height 197
DQN0004A [mm] "SON, 0.65mm pitch"
  rect 0.25x0.31 smd paste-1 mask-0.31: 1(-0.535,0.325) 2(-0.535,-0.325) 3(0.535,-0.325) 4(0.535,0.325)
  rect 0.58x0.58 smd rot 45 paste-0.065 mask-0.05: 5(0,0)
  L1-Top Layer region: -0.66,0.48 -0.2,0.48 -0.2,0.379 -0.409,0.17 -0.66,0.17
  L1-Top Layer region: 0.66,0.48 0.2,0.48 0.2,0.379 0.409,0.17 0.66,0.17
  L1-Top Layer region: 0.66,-0.48 0.2,-0.48 0.2,-0.379 0.409,-0.17 0.66,-0.17
  L1-Top Layer region: -0.66,-0.48 -0.2,-0.48 -0.2,-0.379 -0.409,-0.17 -0.66,-0.17
  silkscreen extent -0.88,-0.7 0.88,0.7, body extent -0.53,-0.53 0.53,0.53, height 0.42
DSG0008A [mm] "SON, 8-Leads, Body 2x2mm, Pitch 0.5mm, Thermal Pad 1.6x0.9mm, TI Recommended"
  rrect40% 0.5x0.25 smd: 1(-0.95,0.75) 2(-0.95,0.25) 3(-0.95,-0.25) 4(-0.95,-0.75) 5(0.95,-0.75) 6(0.95,-0.25) 7(0.95,0.25) 8(0.95,0.75)
  rrect14% 0.9x0.7 on Top Paste: 9(0,0.45) 9(0,-0.45)
  rrect11% 0.9x1.6 smd paste-0.45: 9(0,0)
  silkscreen extent -1.07,-1.15 1.07,1.15, body extent -1,-1 1,1, height 0.77
Fiducial10-20 [mm]
  round 1 smd mask+0.5: 1(0,0)
  L1-Top Layer keep-out circle w1.178: c0,0 r0.5
FP-533980471_HDR4-MFG [mm]
  rrect13% 0.8x1.3 smd paste+0 mask+0: 1(1.875,-2) 2(0.625,-2) 3(-0.625,-2) 4(-1.875,-2)
  rrect5% 2.1x3 smd paste+0 mask+0: 5(-4.425,0.75) 6(4.425,0.75)
  silkscreen extent -4.97,-2.79 4.97,1.95, body extent -5.58,-2.75 5.58,2.35, height 0.25
FP-533981271_HDR12-MFG [mm]
  rrect13% 0.8x1.3 smd paste+0 mask+0: 1(6.875,-1.75) 2(5.625,-1.75) 3(4.375,-1.75) 4(3.125,-1.75) 5(1.875,-1.75) 6(0.625,-1.75) 7(-0.625,-1.75) 8(-1.875,-1.75) 9(-3.125,-1.75) 10(-4.375,-1.75) 11(-5.625,-1.75) 12(-6.875,-1.75)
  rrect5% 2.1x3 smd paste+0 mask+0: 13(-9.425,1) 14(9.425,1)
  silkscreen extent -9.97,-3.17 9.97,1.95, body extent -10.58,-2.5 10.58,2.6, height 0.25
FP-5034801400_SMD_8MM7_3MM6-MFG [mm]
  rrect33% 0.3x0.7 smd paste+0 mask+0: 1(-3.25,1.7) 2(-2.75,1.7) 3(-2.25,1.7) 4(-1.75,1.7) 5(-1.25,1.7) 6(-0.75,1.7) 7(-0.25,1.7) 8(0.25,1.7) 9(0.75,1.7) 10(1.25,1.7) 11(1.75,1.7) 12(2.25,1.7) 13(2.75,1.7) 14(3.25,1.7)
  rrect33% 0.3x1 smd paste+0 mask+0: 15(-4.04,-0.95) 16(4.04,-0.95)
  silkscreen extent -4.5,-2.15 4.5,2.82, body extent -4.6,-2.25 4.6,2.25, height 0.25
HDR1X2 [mm] "Connector; Header; 2 Position"
  rect 1.5x1.5 hole 0.9: 1(0,0)
  round 1.5 hole 0.9: 2(2.54,0)
  silkscreen extent -1.27,-1.27 3.81,1.27
Keystone5005 [mil] "Keystone Compact loops"
  round 87 hole 63: 1(0,0)
  silkscreen extent -70,-70 70,70, body extent -63,-63 62,63, height 225
Label_650x200 [mil] "Thermal Transfer Label"
  round 1 on Mech13: 0(0,0)
  silkscreen extent -325,-100 325,100, body extent -325,-100 325,100, height 1
Pb-Free_Overlay_Small [mil]
  silkscreen extent -46,-46 46,46
RSM0032B-MFG [mm]
  rrect50% 0.55x0.2 smd paste+0 mask+0: 1(-1.925,1.4) 2(-1.925,1) 3(-1.925,0.6) 4(-1.925,0.2) 5(-1.925,-0.2) 6(-1.925,-0.6) 7(-1.925,-1) 8(-1.925,-1.4) 17(1.925,-1.4) 18(1.925,-1) 19(1.925,-0.6) 20(1.925,-0.2) 21(1.925,0.2) 22(1.925,0.6) 23(1.925,1) 24(1.925,1.4)
  rrect50% 0.2x0.55 smd paste+0 mask+0: 9(-1.4,-1.925) 10(-1,-1.925) 11(-0.6,-1.925) 12(-0.2,-1.925) 13(0.2,-1.925) 14(0.6,-1.925) 15(1,-1.925) 16(1.4,-1.925) 25(1.4,1.925) 26(1,1.925) 27(0.6,1.925) 28(0.2,1.925) 29(-0.2,1.925) 30(-0.6,1.925) 31(-1,1.925) 32(-1.4,1.925)
  rrect4% 2.8x2.8 smd paste-1000 mask+0: 33(0,0)
  silkscreen extent -2.92,-2.05 2.05,2.05, body extent -2.3,-2.3 2.3,2.3, height 0.25
RTE0016J [mm] "WQFN-16"
  rrect42% 0.6x0.24 smd: 1(-1.4,0.75) 2(-1.4,0.25) 3(-1.4,-0.25) 4(-1.4,-0.75) 9(1.4,-0.75) 10(1.4,-0.25) 11(1.4,0.25) 12(1.4,0.75)
  rrect42% 0.24x0.6 smd: 5(-0.75,-1.4) 6(-0.25,-1.4) 7(0.25,-1.4) 8(0.75,-1.4) 13(0.75,1.4) 14(0.25,1.4) 15(-0.25,1.4) 16(-0.75,1.4)
  rrect6% 1.66x1.66 smd paste-0.075: 17(0,0)
  silkscreen extent -1.5,-1.5 1.5,1.5, body extent -1.5,-1.5 1.5,1.5, height 0.8
Samtec_TSM-102-01-x-DV [mm] "Header, 2.54mm, 2x2, SMT"
  rect 3.68x1.27 smd: 1(-2.475,1.27) 2(2.475,1.27) 3(-2.475,-1.27) 4(2.475,-1.27)
  silkscreen extent -1.75,-2.54 1.65,2.63, body extent -3.85,-2.54 3.85,2.54, height 9.65
Samtec_TSM-104-01-x-DV [mm] "Header, 2.54mm, 4x2, SMT"
  rect 3.68x1.27 smd: 1(-2.475,3.81) 2(2.475,3.81) 3(-2.475,1.27) 4(2.475,1.27) 5(-2.475,-1.27) 6(2.475,-1.27) 7(-2.475,-3.81) 8(2.475,-3.81)
  silkscreen extent -1.65,-5.08 1.65,5.22, body extent -3.85,-5.08 3.85,5.08, height 9.65
SOD-123F [mm] "NXP recommended land pattern"
  rect 1.2x1.2 smd paste-0.05: 1(-1.4,0) 2(1.4,0)
  silkscreen extent -2.64,-1.12 2.01,1.12, body extent -1.8,-0.85 1.8,0.85, height 1.2
Sullins_GRPB041VWVN-RC [mm] "TH, Header, 1.27 mm, 4x1, Straight"
  rect 1.05x1.05 hole 0.75: 1(-1.905,0)
  round 1.05 hole 0.75: 2(-0.635,0) 3(0.635,0) 4(1.905,0)
  silkscreen extent -2.79,-1.65 2.79,1.07, body extent -2.79,-1.07 2.79,1.07, height 4.3
Sullins_xPxC052LFBN [mm] "Receptacle, 2.54mm, 5x2, TH"
  rect 1.55x1.55 hole 1.02: 1(-5.08,1.27)
  round 1.55 hole 1.02: 2(-5.08,-1.27) 3(-2.54,1.27) 4(-2.54,-1.27) 5(0,1.27) 6(0,-1.27) 7(2.54,1.27) 8(2.54,-1.27) 9(5.08,1.27) 10(5.08,-1.27)
  silkscreen extent -6.6,-2.54 6.6,2.9, body extent -6.6,-2.54 6.6,2.54, height 8.5
SW_1188E [mm] "SMD, 4-Leads, Body 7.8x3.5mm"
  rrect10% 1x1.45 smd: 1(-1.1,3.375) 2(-1.1,-3.375)
  rrect11% 1.3x0.9 smd: 3(0.7,2.1) 4(0.7,-2.1)
  round 0 hole 0.9 unplated mask+0.051: ""(-0.35,-1.15) ""(-0.35,1.15)
  silkscreen extent -1.97,-2.28 0.95,2.28, body extent -2.55,-3.9 1.05,3.9, height 3.5
TP_SM_1MM [mm] "1mm Test Point, SMT"
  round 1 smd paste-0.5: 1(0,0)
WEEE_Minimum [mil] "WEEElie bin"
  silkscreen extent -95,-172 99,104

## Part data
3.3V 3.3V_MCU 5V DECAY_TOFF_0 DECAY_TOFF_2 DIR DIR_0 DIR_1 FOCUS-M-A-N FOCUS-M-A-P FOCUS-M-B-N FOCUS-M-B-P IN1/PHASE IN2/ENBL IRIS-M-A-N IRIS-M-A-P M0_0 M0_1 M1_0 M1_1 SPEED_REF STEP_0 STEP_1 TM_A_N TM_A_P TM_B_N TM_B_P VCC VDD0 VDD1 VM_Focus VM_Iris VM_TM: library part CMP-0003825-1, "1mm Test Point, SMT", Manufacturer=Any
C1 C4: "CAP, CERM, 1 µF, 16 V,+/- 10%, X7R, 0603", Cap_Case=0603, Manufacturer=MuRata, Supplier Part Number 1=490-3900-1-ND, TempCo=X7R, Tolerance_%=10, Value1="0.011 ohm", Value2=16V, ValueDisplayed=1µF
C2 C15: library part CMP-0007885-2, "CAP, CERM, 4.7 uF, 35 V, +/- 10%, X7R, 0805", Cap_Case=0805, Manufacturer=TDK, Supplier Part Number 1=445-7555-1-ND, TempCo=X7R, Tolerance_%=10%, Value1="0.002346 ohm", Value2=35V, ValueDisplayed=4.7uF
C3 C5 C6 C9 C12 C13 C14 C18: library part Cap, "CAP CER 0.1UF 16V 10% X7R 0402", Manufacturer="Murata Electronics North America", MFG Part Number=GRM155R71C104KA88D
C7: "CAP, CERM, 1000 pF, 25 V, +/- 10%, X7R, 0402", Cap_Case=0402, Manufacturer="Wurth Elektronik", Supplier Part Number 1=710-885012205044, TempCo=X7R, Tolerance_%=10, Value1=Unknown, Value2=25V, ValueDisplayed=1000pF
C8: library part CMP-0007497-4, "CAP, CERM, 10 uF, 10 V, +/- 20%, X7R, 0603", Cap_Case=0603, Manufacturer=MuRata, Supplier Part Number 1=81-GRM188Z71A106MA3D, TempCo=X7R, Tolerance_%=20%, Value1=Unknown, Value2=10V, ValueDisplayed=10uF
C10 C11: library part CMP-0006200-2, "CAP, CERM, 100 pF, 16 V, +/- 10%, X7R, 0402", Cap_Case=0402, Manufacturer=AVX, Supplier Part Number 1=478-7887-1-ND, TempCo=X7R, Tolerance_%=10%, Value1=Unknown, Value2=16V, ValueDisplayed=100pF
C16 C17: library part CMP-0064936-4, "CAP, CERM, 4.7 uF, 16 V,+/- 10%, X7R, 0603", Cap_Case=0603, Manufacturer=MuRata, TempCo=X7R, Tolerance_%=10%, Value1=Unknown, Value2=16V, ValueDisplayed=4.7uF
C19 C20: library part CMP-0006674-1, "CAP, CERM, 0.01 uF, 50 V, +/- 10%, X7R, 0402", Cap_Case=0402, Manufacturer=MuRata, Supplier Part Number 1=490-4516-1-ND, TempCo=X7R, Tolerance_%=10%, Value1=Unknown, Value2=50V, ValueDisplayed=0.01uF
C21 C22: library part CMP-0007050-3, "CAP, CERM, 0.47 uF, 50 V, +/- 10%, X7R, 0603", Cap_Case=0603, Manufacturer=TDK, Supplier Part Number 1=445-5952-1-ND, TempCo=X7R, Tolerance_%=10%, Value1="0.010974 ohm", Value2=50V, ValueDisplayed=0.47uF
C23 C24 C25 C26 C27 C28 C29 C30 C31 C32: library part CMP-0006319-1, "CAP, CERM, 3300 pF, 50 V, +/- 10%, X7R, AEC-Q200 Grade 1, 0402", Cap_Case=0402, Manufacturer=TDK, Supplier Part Number 1=445-6891-1-ND, TempCo=X7R, Tolerance_%=10%, Value1="0.785178 ohm", Value2=50V, ValueDisplayed=3300pF
D1: "LED, Green, SMD", Color=Green, Manufacturer=Kingbright, Power_TotalModule=0.075, Supplier Part Number 1=754-1101-1-ND, Value1=0.075W, Value2=2.1V
D2: library part CMP-0028849-2, "Diode, Schottky, 40 V, 2 A, SOD-123F", Manufacturer=Panasonic, Value1=2A, Value2=0.47V
D3 D4 D5: "LED, Red, SMD", Color=Red, Manufacturer=Kingbright, Power_TotalModule=0.075, Supplier Part Number 1=754-1104-1-ND, Value1=0.075W, Value2=1.95V
FID1 FID2 FID3 FID4 FID5 FID6: library part CMP-0077181-1, "Fiducial mark.  There is nothing to buy or mount.", Manufacturer=N/A
GND1 GND2 GND3 GND4: library part CMP-0055142-1, "Test Point, Compact, Red, TH", Color=Red, Manufacturer=Keystone, PartNumber=5005, Supplier Part Number 1=36-5005-ND
H1 H2 H3 H4: library part CMP-0003620-1, "Bumpon, Hemisphere, 0.44 X 0.20, Clear", Manufacturer=3M, Supplier Part Number 1=SJ5303-7-ND
J1 J2: "Header, 50mil, 4x1, Gold, TH", Manufacturer="Sullins Connector Solutions", Supplier Part Number 1=S9014E-04-ND
J3: "CONN HEADER VERT SGL 2POS GOLD", Manufacturer=3M, MFG Part Number=961102-6404-AR
J4: library part CMP-0054661-1, "Receptacle, 2.54mm, 5x2, Gold, TH", Color=Black, Current_A=3A, Manufacturer="Sullins Connector Solutions", Supplier Part Number 1=S6105-ND, Voltage_V=250V
J5 J6: library part CMP-0075593-1, "Header, 2.54mm, 4x2, Gold, SMT", Color=Black, Current_A=4.9A, Manufacturer=Samtec, Supplier Part Number 1=TSM-104-01-L-DV-ND, Voltage_V=475V
J7: library part CMP-0055559-1, "Header, 2.54mm, 2x2, Gold, SMT", Color=Black, Manufacturer=Samtec, Supplier Part Number 1=TSM-102-01-L-DV-ND, Voltage_V=475V
J8 J9 J11: library part CMP-0088984-1, Current_A=1A, Digikey Part Number=WM7608CT-ND, Manufacturer=Molex, Mouser Part Number=538-53398-0471, Operating Temperature Range="-40°C to +105°C", Voltage_V=125V
J10: library part CMP-0088983-1, Current_A=500mA, Digikey Part Number=WM1442CT-ND, Manufacturer=Molex, Mouser Part Number=538-503480-1400, Operating Temperature Range="-40°C to +85°C", Voltage_V=50V
J12: library part CMP-0088985-1, Current_A=1A, Digikey Part Number=WM7616CT-ND, Manufacturer=Molex, Mouser Part Number=538-53398-1271, Operating Temperature Range="-40°C to +105°C", Voltage_V=125V
JP1 JP2 JP3: library part CMP-0075197-1, "Header, 2.54mm, 2x1, TH", Color=Black, Current_A=2A, Manufacturer=3M, Supplier Part Number 1=3M9447-ND, Voltage_V=1kV
L1 L2 L3 L4 L5 L6 L7 L8 L9 L10: library part CMP-0003353-1, "Ferrite Bead, 220 ohm @ 100 MHz, 2.5 A, 0603", Manufacturer=MuRata, Supplier Part Number 1=490-5225-1-ND, Value1="0.04 ohm", Value2=2.5A, ValueDisplayed="220 ohm"
LBL1: library part CMP-0003625-1, "Thermal Transfer Printable Labels, 0.650\" W x 0.200\" H - 10,000 per roll", Manufacturer=Brady, Supplier Part Number 1=97C5133
Logo2: library part CMP-0074769-1
Logo3: library part CMP-0074839-1
R1: library part CMP-0001773-2, "Potentiometer, 10k ohm, 0.25W, TH", Manufacturer=Bourns, Supplier Part Number 1=3310Y-001-103L-ND
R2 R14 R15 R16: "RES, 3.30 k, 1%, 0.05 W, 0201", Manufacturer="Yageo America", Power_W=0.05, Supplier Part Number 1=YAG2285CT-ND, TempCo="200 ppm/C", Tolerance_%=1, Value1=1%, Value2=0.05W, Value_Code=3k30, ValueDisplayed=3.30k
R3 R4 R6 R7 R8 R9 R11 R18 R20 R23 R24 R25 R29 R30 R32 R33 R34 R35 R36 R37 R38: library part CMP-0026992-3, "RES, 0, 5%, 0.1 W, AEC-Q200 Grade 0, 0402", Manufacturer=Panasonic, Power_W=100mW, Supplier Part Number 1=P0.0JCT-ND, TempCo="600 ppm/C", Tolerance_%=5%, Value2=0.1W, Value_Code=0000, ValueDisplayed=0
R5 R10: library part CMP-0026825-1, "RES, 10 k, 5%, 0.063 W, 0402", Manufacturer=Vishay-Dale, Power_W=63mW, Supplier Part Number 1=541-10KJCT-ND, TempCo="200 ppm/C", Tolerance_%=5%, Value2=0.063W, Value_Code=10k0, ValueDisplayed=10k
R12: "RES, 47.0 k, 1%, 0.0625 W, 0402", Manufacturer="Yageo America", Power_W=0.0625, Supplier Part Number 1=311-47.0KLRCT-ND, TempCo="100 ppm/C", Tolerance_%=1, Value1=1%, Value2=0.0625W, Value_Code=47k0, ValueDisplayed=47.0k
R13 R26 R27 R28 R31: library part Res1, "RES 1.0K OHM 1/10W 5% 0402 SMD", Manufacturer="Panasonic - ECG", MFG Part Number=ERJ-2GEJ102X
R17 R19: library part CMP-0026731-1, "RES, 330 k, 1%, 0.0625 W, 0402", Manufacturer="Yageo America", Power_W=62.5mW, Supplier Part Number 1=311-330KLRCT-ND, TempCo="100 ppm/C", Tolerance_%=1%, Value2=0.0625W, Value_Code=330k
R21 R22: library part CMP-0026158-2, "RES, 200 k, 1%, 0.063 W, AEC-Q200 Grade 0, 0402", Manufacturer=Vishay-Dale, Power_W=63mW, Supplier Part Number 1=541-200KLCT-ND, TempCo="100 ppm/C", Tolerance_%=1%, Value2=0.063W, Value_Code=200k
R39 R40: library part CMP-0026017-1, "RES, 14.7 k, 1%, 0.063 W, 0402", Manufacturer=Vishay-Dale, Power_W=63mW, Supplier Part Number 1=541-14.7KLCT-ND, TempCo="100 ppm/C", Tolerance_%=1%, Value2=0.063W, Value_Code=14k7, ValueDisplayed=14.7k
R41 R42: library part CMP-0026383-2, "RES, 44.2 k, 1%, 0.063 W, AEC-Q200 Grade 0, 0402", Manufacturer=Vishay-Dale, Power_W=63mW, Supplier Part Number 1=541-44.2KLCT-ND, TempCo="100 ppm/C", Tolerance_%=1%, Value2=0.063W, Value_Code=44k2, ValueDisplayed=44.2k
R43 R44: library part CMP-0026753-1, "RES, 100 k, 1%, 0.063 W, AEC-Q200 Grade 0, 0402", Manufacturer="Stackpole Electronics Inc", Power_W=63mW, Supplier Part Number 1=RMCF0402FT100KCT-ND, TempCo="100 ppm/C", Tolerance_%=1%, Value2=0.063W, Value_Code=100k
R45 R46: library part CMP-0026193-2, "RES, 249 k, 1%, 0.063 W, AEC-Q200 Grade 0, 0402", Manufacturer=Vishay-Dale, Power_W=63mW, Supplier Part Number 1=541-249KLCT-ND, TempCo="100 ppm/C", Tolerance_%=1%, Value2=0.063W, Value_Code=249k
S1: library part CMP-0002328-1, "Switch, SPST, 0.05 A, 12 VDC, SMD", CurrentRating_mA=50A, Manufacturer=Diptronics
U1: library part CMP-0079101-2, "200-mA, Small Size, Low-Dropout Linear Voltage Regulator, DQN0004A (X2SON-4)", Alternate Manufacturer="Texas Instruments"
U2: library part CMP-0089265-1, "CPU16 MSP430™ FRAM Microcontroller IC 16-Bit 24MHz 32KB (32K x 8) FRAM 32-VQFN (4x4)", Digikey Part Number=296-MSP430FR2155TRSMTTR-ND, Frequency_Fixed=24MHz, Manufacturer="Texas Instruments", Max Supply Voltage=3.6V, Min Supply Voltage=1.8V, Mouser Part Number=595-SP430FR2155TRSMT, Nominal Supply Current=185-280uA, Operating Temperature Range="-40°C to +105°C"
U3 U4: library part CMP-0861028-1, "Stepper Drivers With Integrated Current Sense, 1/256 Microstepping, STEP/DIR Interface and smart tune Technology, RTE0016J (WQFN-16)", Alternate Manufacturer="Texas Instruments"
U5: library part CMP-0013449-3, "1-A Low-Voltage H-Bridge Driver, DSG0008A (WSON-8)", Alternate Manufacturer="Texas Instruments"
ZZ1: library part CMP-0077238-1
ZZ2: library part CMP-0077237-1
ZZ3: library part CMP-0077236-1
ZZ4: library part CMP-0003616-3

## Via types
v1: diameter 24, hole 12, L1-Top Layer to L4-Bottom Layer, tented both sides, 151 vias
v2: diameter 30, hole 16, L1-Top Layer to L4-Bottom Layer, tented both sides, 20 vias
v3: diameter 20, hole 10, L1-Top Layer to L4-Bottom Layer, tented both sides, 18 vias
v4: diameter 19.68, hole 7.87, L1-Top Layer to L4-Bottom Layer, 17 vias

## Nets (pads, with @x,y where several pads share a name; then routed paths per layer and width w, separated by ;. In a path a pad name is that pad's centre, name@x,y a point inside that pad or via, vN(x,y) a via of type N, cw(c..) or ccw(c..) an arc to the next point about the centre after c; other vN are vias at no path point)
3.3V: J1.1 J2.4 J10.12 J12.6 JP1.1 R2.2 R3.2 R4.2 R5.2 R10.2 R11.1 R12.2 R14.2 R15.2 R16.2 R18.1 R25.1 | length 522
  L1-Top Layer w10: v1(1150.62,882) R15.2@1178.63,882 ; J10.12@2288.07,1668.58 2319.09,1668.58 v1(2320,1667.68)
  L1-Top Layer w15: v1(49.69,378.11) 50,378.42 R2.2@50,409.02 ; v1(88.26,593.58) R4.2@123.29,593.58 ; v1(127,630.62) 127.23,630.39 R4.2@127.23,593.58 v1(127.23,558.03) ; R3.2@155.62,1780 v1(196,1780) ; R5.2@234.62,659.5 274,659.5 v1(273.25,658.75) ; R10.2@234.62,900.5 v1(234.62,936.31) ; v1(436.28,1102) R12.2@472,1102 ; v1(703,1398) 703,1360.56 R14.2@703.12,1360.44 ; v1(1153.31,241.34) R16.2@1200.01,241.34 ; v1(1401.41,1484.68) R18.1@1401.41,1518 ; v1(2366.07,490) 2366.37,490.3 J12.6@2418.9,490.3
  other v1: 375.26,985.2 341.4,992 395,1015.02 340,1031.14 365,1053.92 1536.06,1443.79 1581.37,1448 1555.31,1470 1524,1473.92 1527.3,1506
5V: 5V.1 C2.1 C4.1 C6.2 D2.1 R32.1 R33.1 R34.1 U1.3 U1.4 | length 143.8
  L1-Top Layer w15: C6.2@371.56,481.04 391.63,481.04 404.67,468 v1(427,468) ; 383.91,570.94 384.54,570.31 v1(425.56,570.31) ; 390,536.47 v1(425.56,536.47) ; R33.1@1733.38,956.09 R33.1@1734.76,954.72
  L1-Top Layer w20: R34.1@1739.39,1408.17 1739.39,1410.02 R34.1@1740.56,1411.2
  other v1: 1745.35,321.18 1775.52,326 1719,335.62 1788.62,354.87 1766,374 427.27,500.97 394,608 425.56,607.69 459,607.69 1755.39,901 1786,908 1728.39,919 1794.2,937.66 1772,959 1758.38,1356 1791,1370 1728.6,1372 1798.34,1400.52 1772,1417
CAM_M_MAX: J12.2 U2.7 | length 2094.5
  L1-Top Layer w8: v3(562,954) 597,989 597,1007.8 606.69,1017.49 U2.7@620.81,1017.49 ; v1(1452.76,822) 2142.92,822 2275.59,689.32 J12.2@2430,689.32
  L4-Bottom Layer w8: v3(562,954) 587,979 697.12,979 854.12,822 v1(1452.76,822)
CAM_M_MIN: J12.4 U2.8 | length 2068
  L1-Top Layer w8: v3(583.5,931.5) 620.81,968.82 U2.8@620.81,1001.74 ; v1(1406.5,792) 2136.23,792 2337.23,591 J12.4@2403,591
  L4-Bottom Layer w8: v3(583.5,931.5) 609.8,957.8 685.33,957.8 851.13,792 v1(1406.5,792)
DECAY_TOFF_0: DECAY_TOFF_0.1 R35.1 R37.2 R39.2 R41.2 R43.2 R45.2 U3.9 | length 483.9
  L1-Top Layer w8: v1(1443.38,1260.37) 1443.38,1240.99 1450.38,1233.99 DECAY_TOFF_0.1@1480,1233.99 1513.66,1233.99 1547.87,1199.78 U3.9@1618.77,1199.78
  L4-Bottom Layer w8: R45.2@1206.18,1292.01 R43.2@1256.18,1292.01 R41.2@1305.27,1292.01 R39.2@1353.11,1292.01 R37.2@1401.09,1292.01
  L4-Bottom Layer w10: R37.2@1401.09,1292.01 1441.13,1292.01 1443.38,1294.26 v1(1443.38,1260.37)
DECAY_TOFF_1: DECAY_TOFF_2.1 R36.1 R38.2 R40.2 R42.2 R44.2 R46.2 U4.9 | length 464.9
  L1-Top Layer w8: DECAY_TOFF_2.1@1517,662 1569.31,609.68 U4.9@1619.76,609.68
  L1-Top Layer w10: v1(1460.83,670.38) 1508.62,670.38 DECAY_TOFF_2.1@1517,662
  L4-Bottom Layer w8: R46.2@1180.47,669.21 R44.2@1230.47,669.21 R42.2@1280.47,669.21 R40.2@1330.47,669.21 R38.2@1380.47,669.21
  L4-Bottom Layer w10: R38.2@1380.47,669.21 1419.83,669.21 1421,670.38 v1(1460.83,670.38)
DIR: DIR.1 JP1.2 R13.1 U2.30 | length 447.7
  L1-Top Layer w8: U2.30@672.98,1132.65 672.98,1422.11 R13.1@736.21,1485.33 736.21,1551.07 JP1.2@738.36,1553.23
DIR_0: DIR_0.1 J5.1 U3.12 | length 423.8
  L1-Top Layer w8: DIR_0.1@1381.2,1051.37 1487.37,1051.37 1576.73,1140.73 U3.12@1618.77,1140.73
  L1-Top Layer w10: J5.1@1247,1015 1295,1015 1331.37,1051.37 DIR_0.1@1381.2,1051.37
DIR_1: DIR_1.1 J6.1 U4.12 | length 431.9
  L1-Top Layer w8: J6.1@1254,390.87 1347.9,390.87 1427.02,470 DIR_1.1@1482,470 1510.5,470 1591.13,550.63 U4.12@1619.76,550.63
FOCUS-M-A-N: FOCUS-M-A-N.1 J11.4 L6.1 U3.1 | length 1043.1
  L1-Top Layer w10: U3.1@1729.01,1140.73 1740.62,1140.73 1751,1130.35
  L1-Top Layer w15: 1751,1130.35 1834.91,1046.44 FOCUS-M-A-N.1@1840,1046.44 1885.07,1046.44 v2(1953.63,1115) 1953.63,1315.13 L6.1@2008.5,1370 ; v2(2365,1071.18) J11.4@2418.74,1071.18
  L4-Bottom Layer w15: v2(1953.63,1115) 1997.45,1071.18 v2@2355,1071.18
FOCUS-M-A-P: FOCUS-M-A-P.1 J11.3 L3.1 U3.2 | length 1019.5
  L1-Top Layer w15: 1760,1157.22 1793.18,1157.22 1835.86,1114.54 FOCUS-M-A-P.1@1840,1114.54 1874.54,1114.54 v2(1920,1160) 1920,1343.84 L3.1@2007.7,1431.55 ; v2(2365,1120.39) J11.3@2418.74,1120.39
  L4-Bottom Layer w15: v2(1920,1160) 1965.68,1160 2005.29,1120.39 v2(2365,1120.39)
FOCUS-M-B-N: FOCUS-M-B-N.1 J11.2 L4.1 U3.3 | length 1051.6
  L1-Top Layer w10: U3.3@1729.01,1180.1 1757.23,1180.1
  L1-Top Layer w15: 1757.23,1180.1 1837.45,1180.1 FOCUS-M-B-N.1@1840,1182.65 v2(1885,1227.65) 1885,1372.3 L4.1@2007.7,1495 ; v2(2365,1169.61) J11.2@2418.74,1169.61
  L4-Bottom Layer w15: v2(1885,1227.65) 1978.72,1227.65 2036.76,1169.61 v2(2365,1169.61)
FOCUS-M-B-P: FOCUS-M-B-P.1 J11.1 L5.1 U3.4 | length 1127.9
  L1-Top Layer w10: U3.4@1729.01,1199.78 1745.44,1199.78 1751.39,1205.74
  L1-Top Layer w15: 1751.39,1205.74 1790.13,1205.74 1835.14,1250.75 FOCUS-M-B-P.1@1840,1250.75 1840,1310.95 v2(1838.73,1312.22) 1838.73,1388.38 L5.1@2007.7,1557.36 ; v2(2365,1218.82) J11.1@2418.74,1218.82
  L4-Bottom Layer w15: v2(1838.73,1312.22) 1976.85,1312.22 2070.25,1218.82 v2(2365,1218.82)
FOCUS_EN: R21.1 U2.24 | length 787.9
  L1-Top Layer w8: U2.24@772.39,1111.98 840.11,1111.98 v3(862,1133.86)
  L1-Top Layer w10: v1(1375.56,1001.74) 1375.56,1000.18 1404.95,970.79 R21.1@1454.76,970.79
  L4-Bottom Layer w8: v3(862,1133.86) 862,1086 946.26,1001.74 v1(1375.56,1001.74)
FOCUS_EN_nFAULT: C10.1 JP2.2 R21.2 U3.13 | length 331.2
  L1-Top Layer w8: C10.1@1509.73,1012.56 1509.73,1022.48 1602.39,1115.14 U3.13@1644.36,1115.14
  L1-Top Layer w10: C10.1@1500,1020 1500,972.79 R21.2@1502,970.79 1502,915 1484,897 JP2.2@1501,897
FOCUS_nFAULT: D4.2 JP2.1 U2.25 | length 893
  L1-Top Layer w8: U2.25@751.72,1132.65 751.72,1142.54 761.18,1152 807.06,1152 v3(817,1142.06)
  L1-Top Layer w10: D4.2@1279,880.05 JP2.1@1383.1,880.05
  L4-Bottom Layer w8: v3(817,1142.06) 817,1078.5 941.5,954 1312.53,954 1369.53,897 JP2.1@1384,897
FOCUS_nSLEEP: R24.2 R30.1 U2.26 U3.14 | length 1208.5
  L1-Top Layer w8: U2.26@735.97,1132.65 735.97,1151.61 758.24,1173.87 838.13,1173.87 v3(839,1173) ; v1(1542.66,974) 1542.66,1004.03 1551.77,1013.15 R24.2@1580.46,1013.15 R30.1@1630.46,1013.15 1630.46,1063.27 1664.05,1096.85 U3.14@1664.05,1115.14
  L4-Bottom Layer w8: v3(839,1173) 839,1082 947,974 v1(1542.66,974)
GND: C1.2 C2.2 C3.1 C4.2 C5.1 C6.1 C7.2 C8.2 C9.1 C10.2 C11.2 C12.1 C13.1 C14.1 C15.2 C16.2 C17.2 C18.1 C19.2 C20.2 C21.2 C22.2 C23.2 C24.1 C25.1 C26.1 C27.2 C28.2 C29.2 C30.2 C31.1 C32.1 D1.2 GND1.1 GND2.1 GND3.1 GND4.1 J1.4 J2.1 J3.2 J4.2 J4.10 J8.5 J8.6 J9.5 J9.6 J10.15 J10.16 J11.5 J11.6 J12.3 J12.5 J12.8 J12.13 J12.14 R1.1 R13.2 R17.1 R19.1 R20.2 R23.2 R26.2 R27.2 R30.2 R37.1 R38.1 R39.1 R40.1 R41.1 R42.1 R43.1 R44.1 R45.1 R46.1 S1.1 S1.2 S1.4 U1.2 U1.5 U2.6 U2.33 U3.5 U3.16 U3.17 U4.5 U4.16 U4.17 U5.4 U5.9@1676.8,1664.15 | length 4393.3
  L1-Top Layer w8: C9.1@562,1000.27 562,1001 594.24,1033.24 U2.6@620.81,1033.24 ; U2.6@627.41,1033.24 U2.33@653,1033.24 ; v4(696.6,1056.86) U2.33@745.81,1106.07 ; U3.16@1703.42,1115.14 1718.22,1115.14 ; U4.16@1704.41,525.04 1719.17,525 ; U4.5@1704.41,635.28 1726.06,635.28 ; C20.2@1737.82,481.04 1741.52,484.74 C20.2@1741.52,477.75
  L1-Top Layer w10: v1(63,1272) 63,1224.66 S1.1@64.13,1223.53 ; S1.2@64.13,957.78 64.91,957 v1(107,957) ; S1.4@135,1007.98 v1(180,1007.98) ; R13.2@775.58,1485.33 v1(775.58,1517.28) ; v1(1436.18,415) 1437.73,416.55 C11.2@1474,416.55 ; C14.1@1599.09,1269.07 1602.77,1272.76 1602.77,1302.99 R27.2@1607.32,1307.54 ; U5.9@1684.2,1684.3 1693.57,1693.67 U5.4@1714.2,1693.67 ; v1(2110,1630.7) 2147.05,1630.7 C28.2@2147.76,1630 ; v1(2115,1385) 2145.72,1385 C24.1@2146.05,1385.33 ; v1(2115,1445) 2145.35,1445 C25.1@2146.05,1445.7 ; v1(2115,1505) 2145.35,1505 C26.1@2146.05,1505.7 ; v1(2115,1565) 2145.35,1565 C27.2@2146.05,1565.7 ; v1(2145,1725.47) 2145,1695.05 C23.2@2146.38,1693.67 ; v1(2148.3,250.33) C29.2@2185.35,250.33 ; v1(2148.3,317.26) C30.2@2185.35,317.26 ; v1(2148.3,384.19) C31.1@2185.35,384.19 ; v1(2148.3,451.12) C32.1@2185.35,451.12 ; v1(2345,1420.94) J10.15@2392.4,1420.94 v1(2439.8,1420.94) ; v1(2395,1766.18) 2395,1741.65 J10.16@2392.4,1739.06 v1(2435,1739.06)
  L1-Top Layer w15: v1(49.68,555.1) 50,554.79 D1.2@50,513.97 ; v1(435.7,1152) C7.2@472,1152 ; v1(489,932) 489,930 488,929 487,930 487,959.65 C8.2@507,979.65 528,958.65 v1(528,934) ; v1(1341,1170.25) 1383.87,1170.25 R17.1@1385.49,1171.87 ; v1(1354.29,588.73) R19.1@1401.01,588.73 ; v1(1410.04,1020) C10.2@1452.76,1020 ; v1(1450,1484.68) R20.2@1450,1518 ; v1(1532.65,1829.74) 1590.69,1829.74 1600.79,1839.84 J8.6@1600.79,1825.47 v1(1666.39,1825.47) ; v1(1545,189.45) 1673.27,189.45 v1(1673.89,190.07) ; v1(1558.82,728) 1592.68,728 R26.2@1591.94,727.26 ; v1(1561,1311) 1596.12,1311 1596.18,1310.95 1597.45,1312.22 1602.14,1307.54 R27.2@1606.82,1312.22 ; v1(1579.32,336.02) R23.2@1579.32,378.74 ; C13.1@1590.78,685.67 1593.35,688.25 1593.35,725.86 R26.2@1591.94,727.26 ; R26.2@1591.94,727.36 R26.2@1591.94,727.26 ; R26.2@1593.45,727.36 1593.35,727.26 R26.2@1591.94,727.26 ; v1(1630.46,923.62) R30.2@1630.46,965.9 ; 1718.22,1115.14 1733.38,1099.97 C19.2@1733.38,1066.72 1733.38,1029.05 C17.2@1750.71,1011.72 ; 1719.17,525 1730,525.04 1737.82,517.22 C20.2@1737.82,481.04 ; 1726.06,635.28 1763.25,672.47 C22.2@1763.25,681.84 ; C20.2@1735.4,478.69 1735.4,433.58 C16.2@1744.77,424.21 ; C21.2@1756.85,1272.95 1758.82,1274.92 v1(1758.82,1310) ; C21.2@1758.82,1271.73 v1(1800,1271.73) ; v1(1790.13,709.45) 1790.87,709.45 C22.2@1763.25,681.84 ; v1(1790.87,436.77) 1757.33,436.77 C16.2@1744.77,424.21 ; v1(1793.18,405) 1789.18,409 1764.82,409 1749.61,424.21 C16.2@1744.77,424.21 ; v1(1799.61,1030) 1768.98,1030 C17.2@1750.71,1011.72 ; v1(1801,993.88) 1799.12,992 1770.43,992 C17.2@1750.71,1011.72 ; v1(1804.59,676) 1771.09,676 1770.09,675 C22.2@1763.25,681.84 ; v1(1885,1818.42) 1942.16,1818.42 J8.5@1949.21,1825.47 1949.68,1825 v1(2015,1825) ; v1(1895.08,179.53) J9.6@1959.21,179.53 2023.35,179.53 v1(2023.97,180.15) ; v1(2224.84,970.79) J11.5@2310.47,970.79 v1(2396.1,970.79) ; v1(2224.84,1319.21) J11.6@2310.47,1319.21 v1(2396.1,1319.21) ; v1(2225,94.63) J12.13@2310.63,94.63 v1(2396.26,94.63) ; v1(2225,836.76) J12.14@2310.63,836.76 v1(2396.26,836.76) ; v1@2366.37,391.88 J12.8@2418.9,391.88 ; v1@2366.37,539.51 J12.5@2418.9,539.51 ; v1@2366.37,637.94 J12.3@2418.9,637.94
  L1-Top Layer w20: v1(1634.8,1470) 1634.8,1490.52 C15.2@1672.23,1527.95 ; v1(1673.44,1471.23) C15.2@1673.44,1524.4 ; C15.2@1673.44,1551.18 C15.2@1673.44,1524.4 ; U5.9@1676.8,1664.15 v4(1676.8,1642.49) 1676.8,1589.39 C18.1@1675.69,1588.28 1675.69,1524.4 C15.2@1673.44,1524.4
  L4-Bottom Layer w15: R46.1@1180.47,716.45 v1(1180.47,759.17) ; R45.1@1206.18,1339.26 v1(1206.18,1381.97) ; R44.1@1230.47,716.45 v1(1230.47,759.17) ; R43.1@1256.18,1339.26 v1(1256.18,1381.97) ; R42.1@1280.47,716.45 v1(1280.47,759.17) ; R41.1@1305.27,1339.26 v1(1305.27,1381.97) ; R40.1@1330.47,716.45 v1(1330.47,759.17) ; R39.1@1353.11,1339.26 v1(1353.11,1381.97) ; R38.1@1380.47,716.45 v1(1380.47,759.17) ; R37.1@1401.18,1339.35 v1(1401.18,1382.06)
  other v1: 290.92,151.76 322.85,184.8 255,342.66 254.31,375 2366.07,391.57 273.5,433 237,434 1776.66,463.29 237,476 300,481.72 2366.07,539.21 2366.07,637.64 1817.78,701 510,908 1794.3,1307.54 1622.71,1551.18 1677,1615.09 1675.35,1717.27 1631.85,1720 1714.2,1720
  other v3: 349.28,551.41
  other v4: 1652.05,557.32 1697.72,557.32 1674.88,580.16 1652.05,602.99 1697.72,602.99 696.6,1011.58 651.33,1056.86 741.88,1056.86 696.6,1102.13 1651.06,1147.42 1696.72,1147.42 1673.89,1170.25 1651.06,1193.09 1696.72,1193.09 1676.8,1685.8
IN1/PHASE: IN1/PHASE.1 J7.1 U5.6 | length 276
  L1-Top Layer w8: J7.1@1384.44,1655.18 1432.31,1655.18 1467.13,1690 IN1/PHASE.1@1513.28,1690 1558.3,1690 1574.31,1673.99 U5.6@1639.4,1673.99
